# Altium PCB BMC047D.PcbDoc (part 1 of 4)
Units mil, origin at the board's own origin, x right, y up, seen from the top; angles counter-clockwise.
Board outline 4950 x 3450 mil, 6 copper layers (Top Layer, GND Layer 1, Signal Layer 1, Signal Layer 2, GND Layer 2, Bottom Layer), stack 60.7 mil thick; 323 components, 167 nets, 1114 pads, 795 vias.
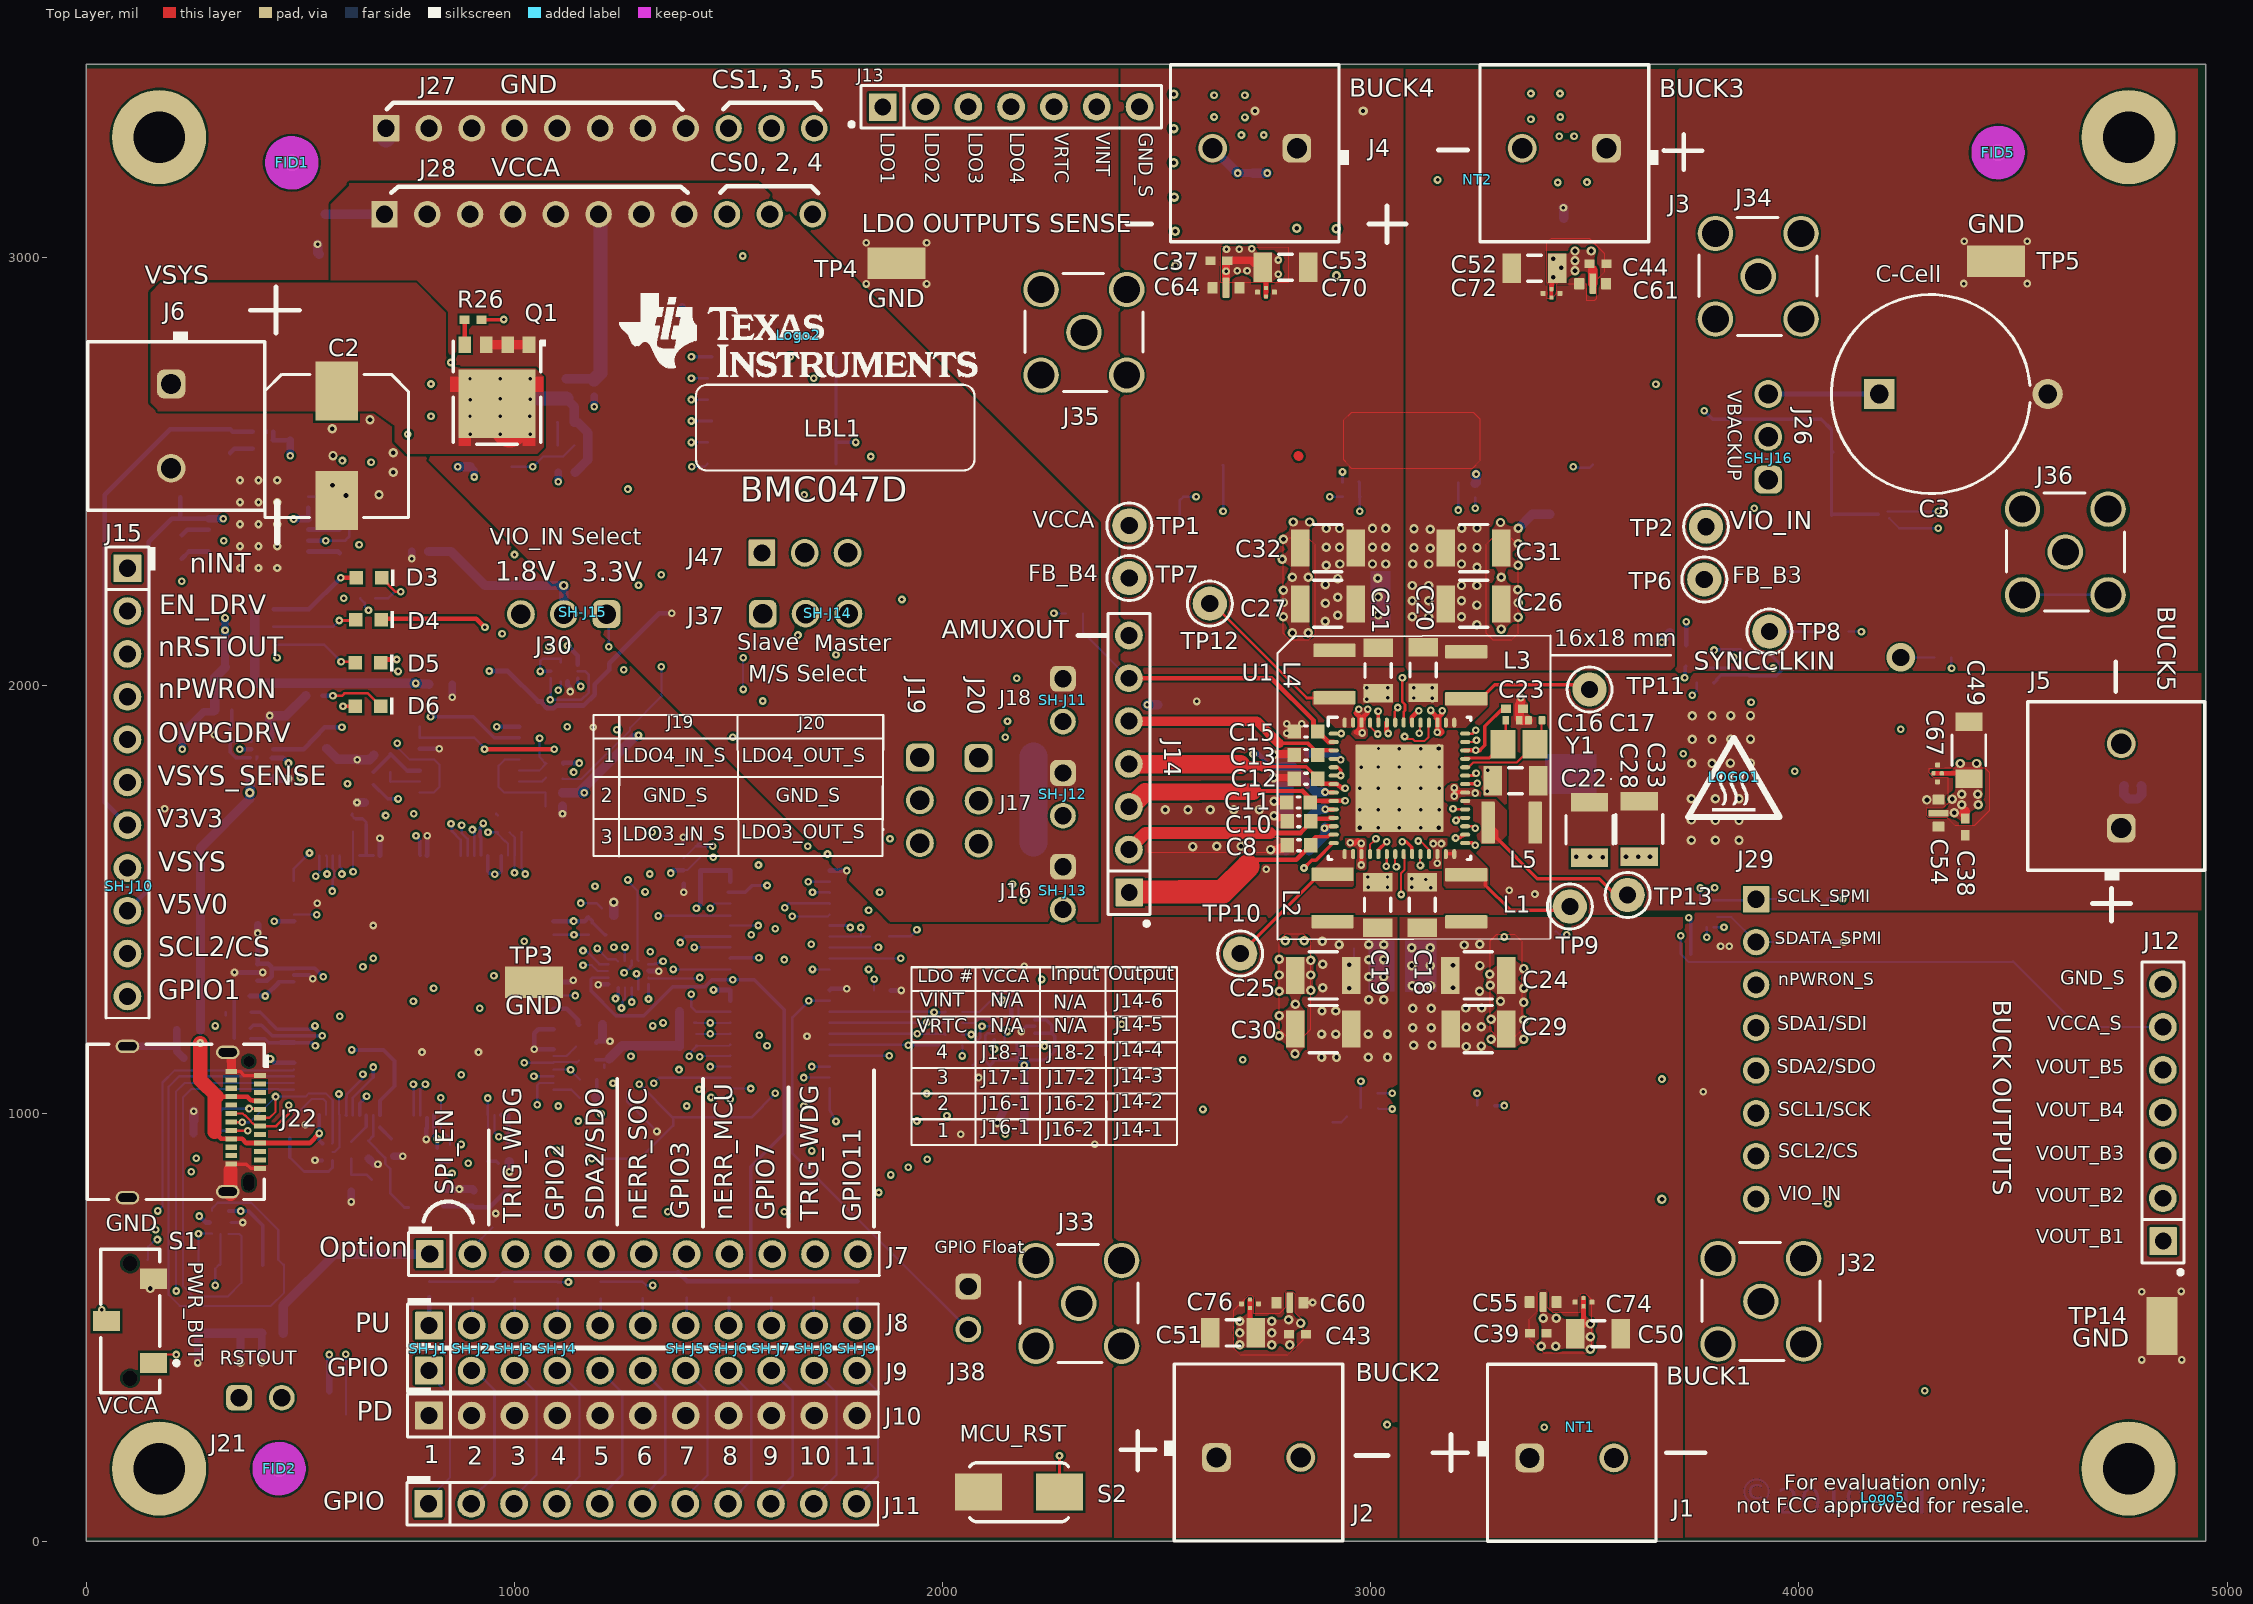
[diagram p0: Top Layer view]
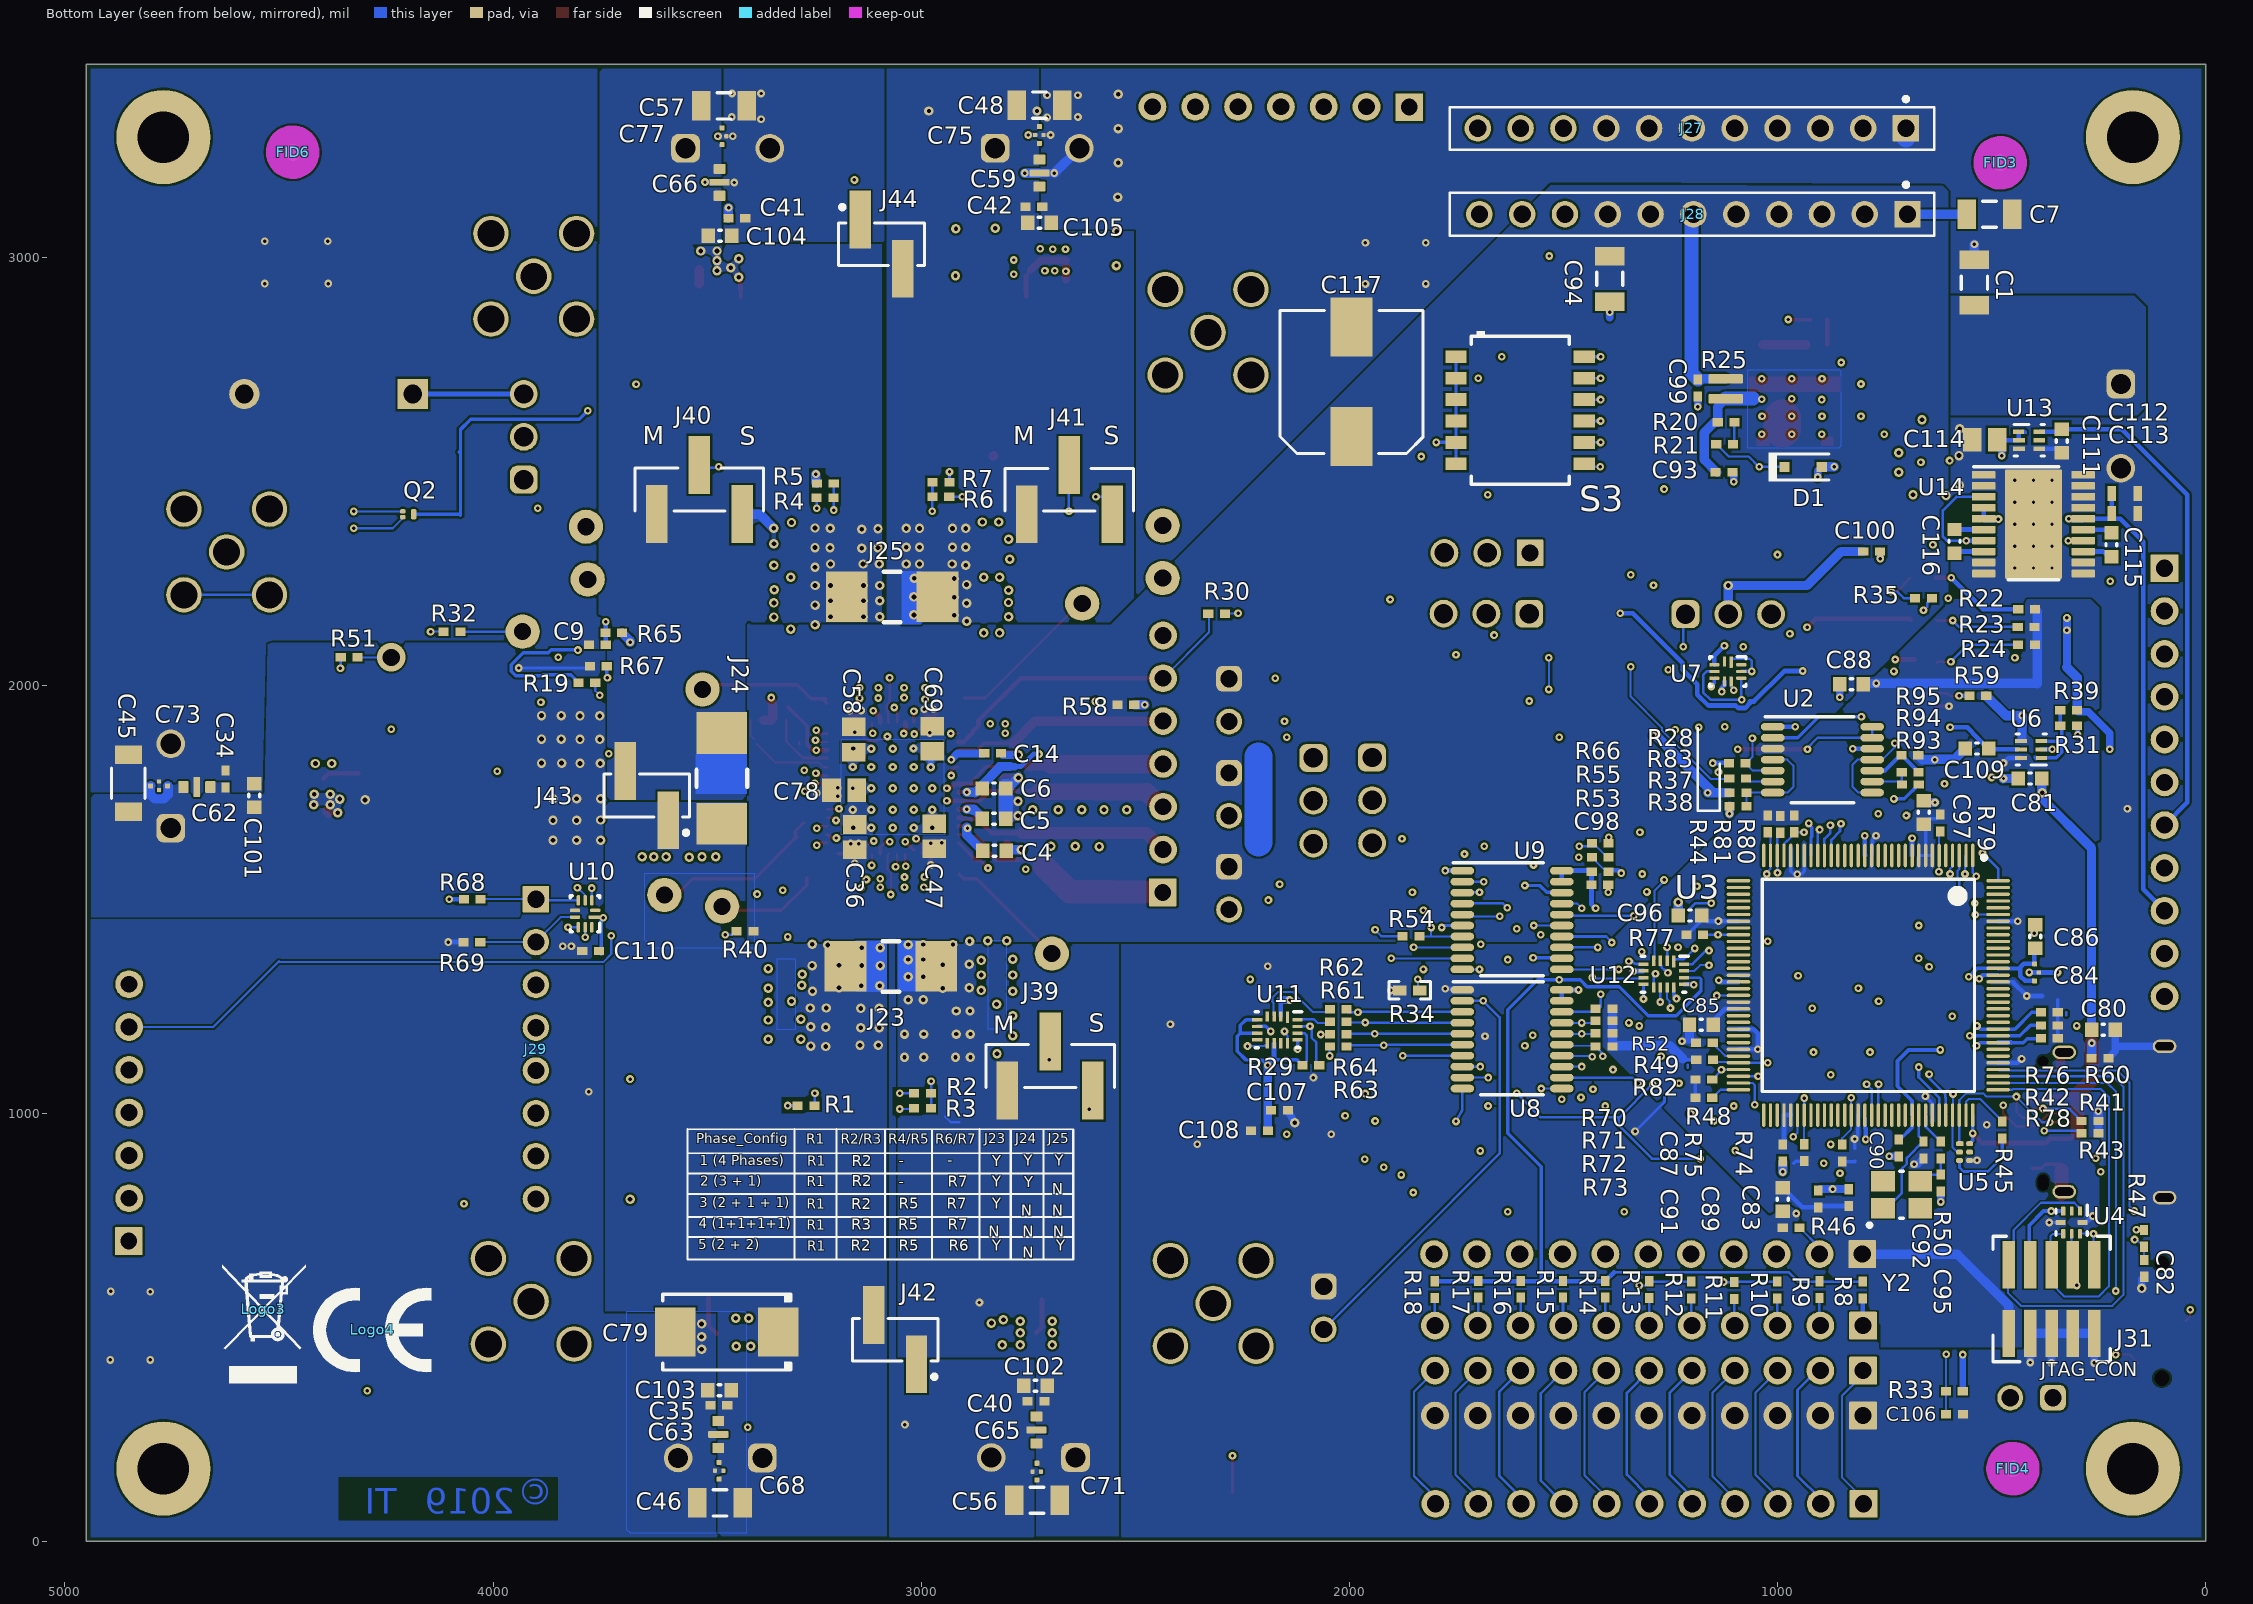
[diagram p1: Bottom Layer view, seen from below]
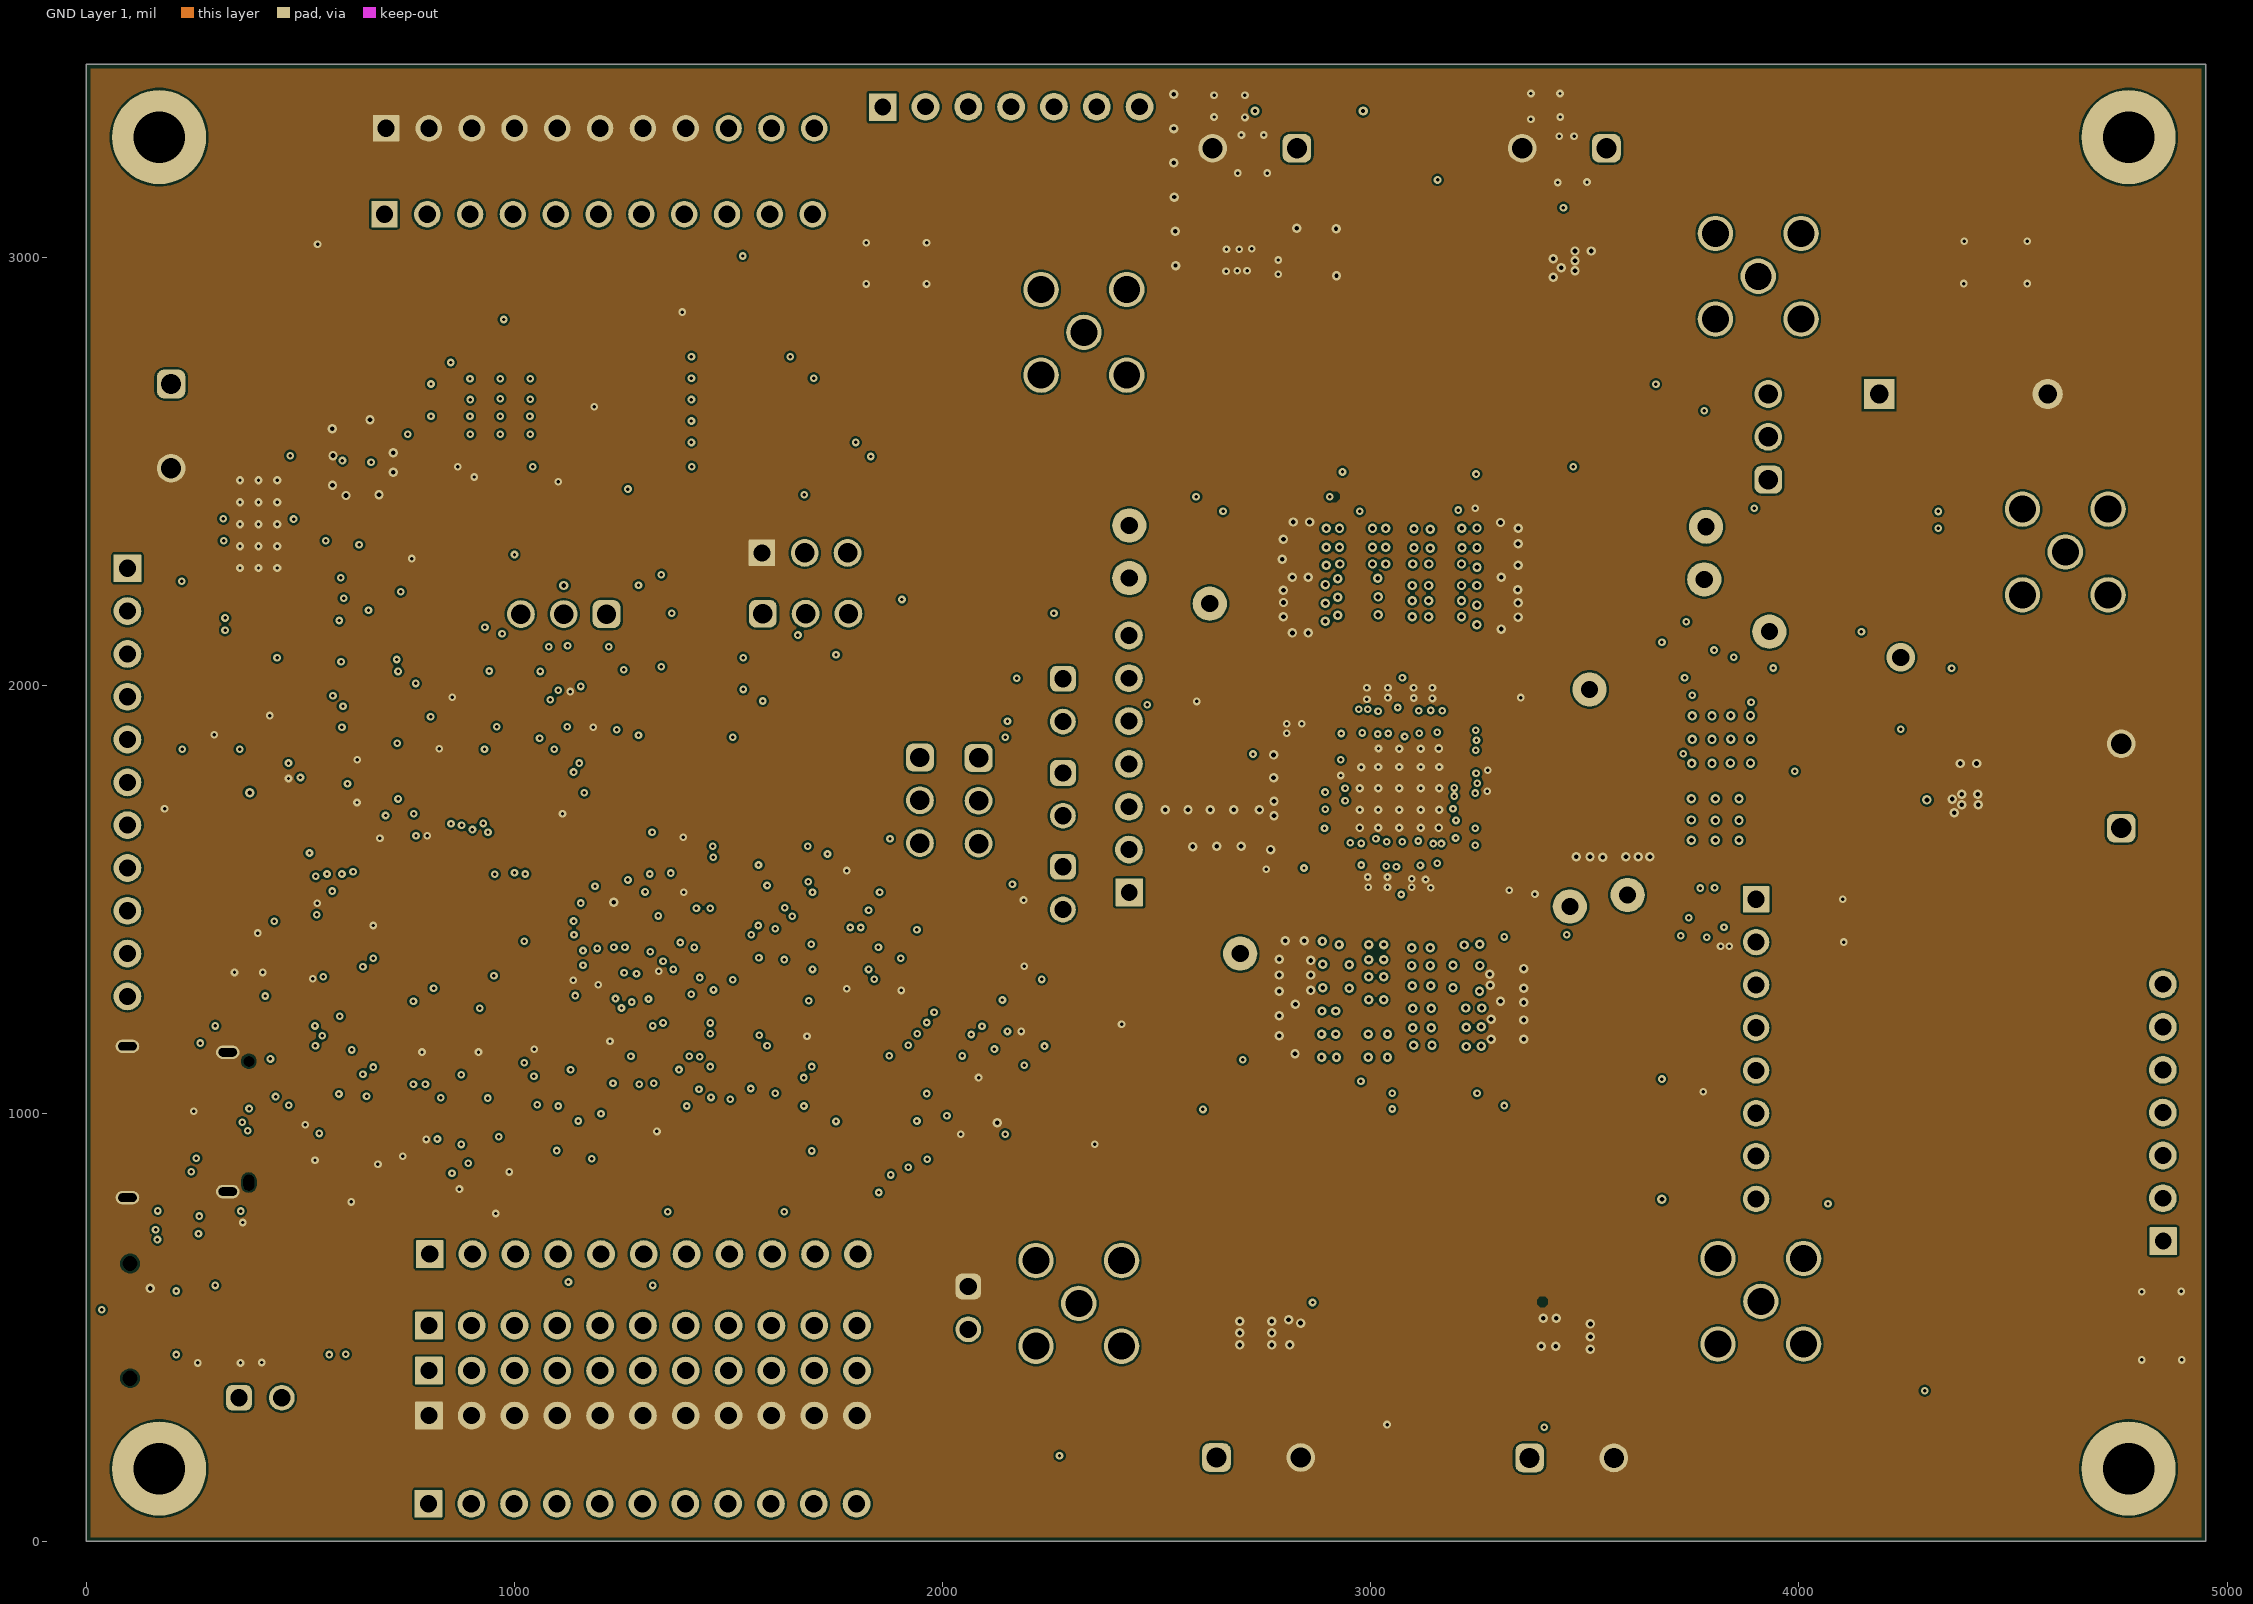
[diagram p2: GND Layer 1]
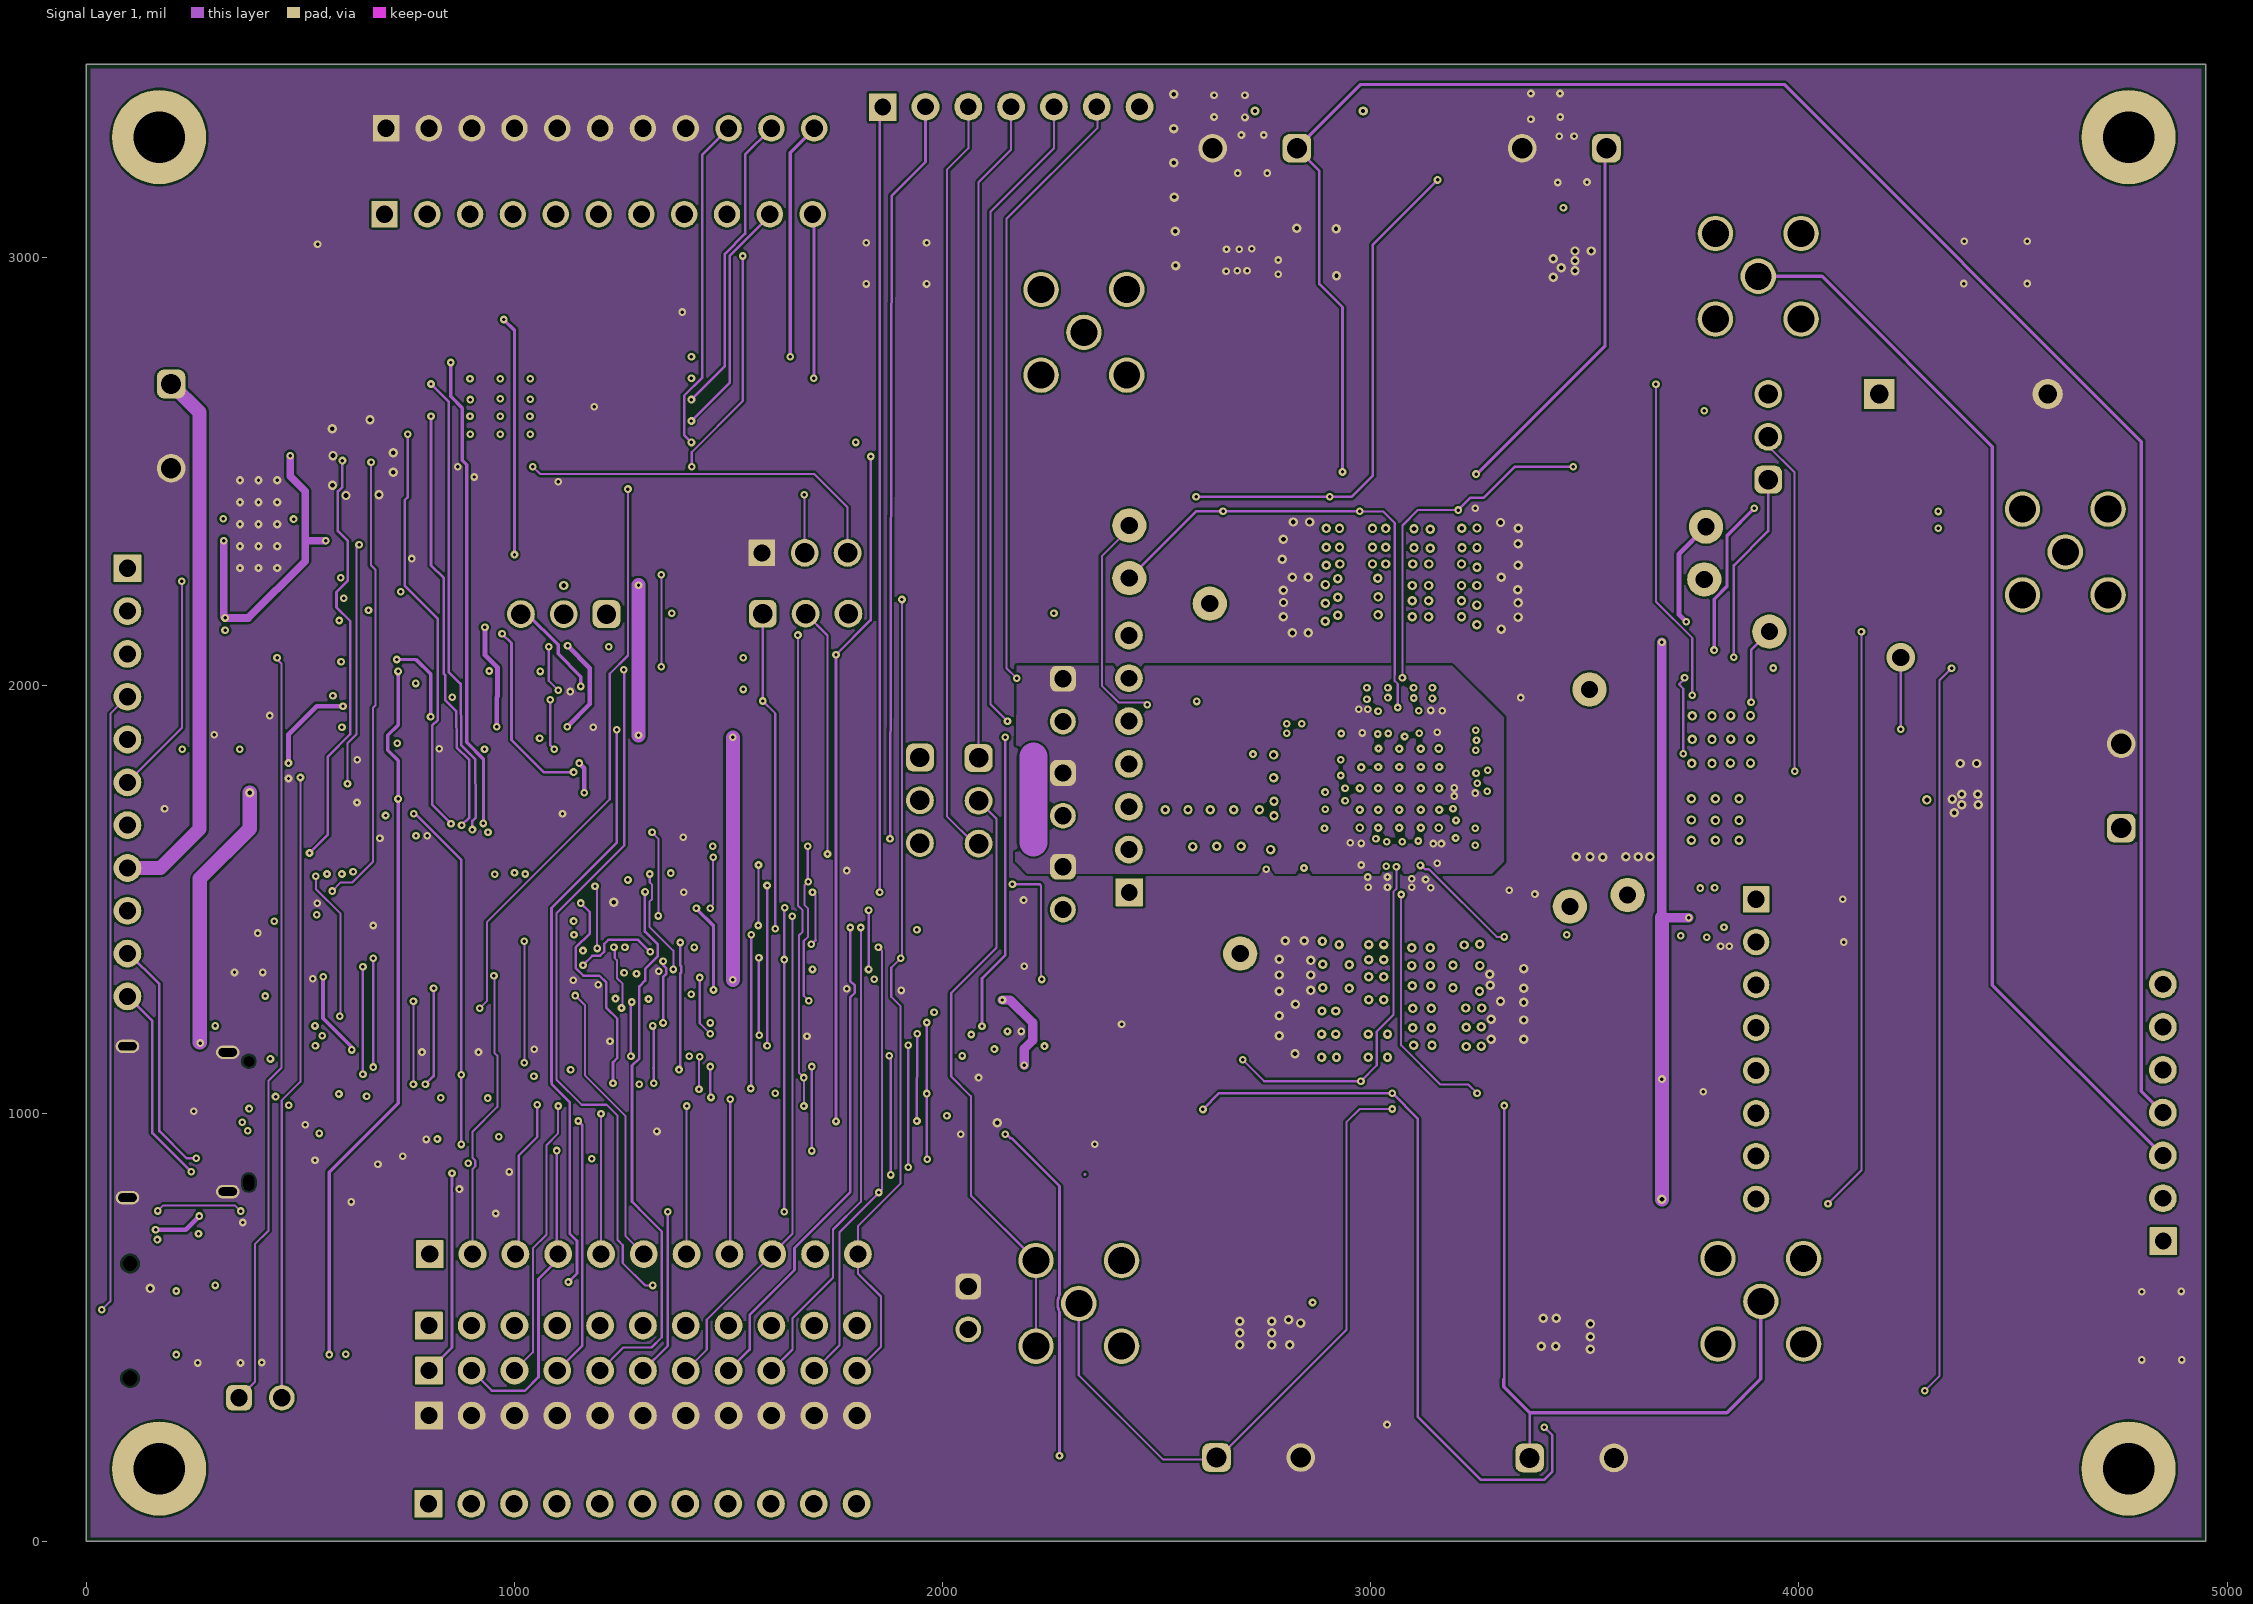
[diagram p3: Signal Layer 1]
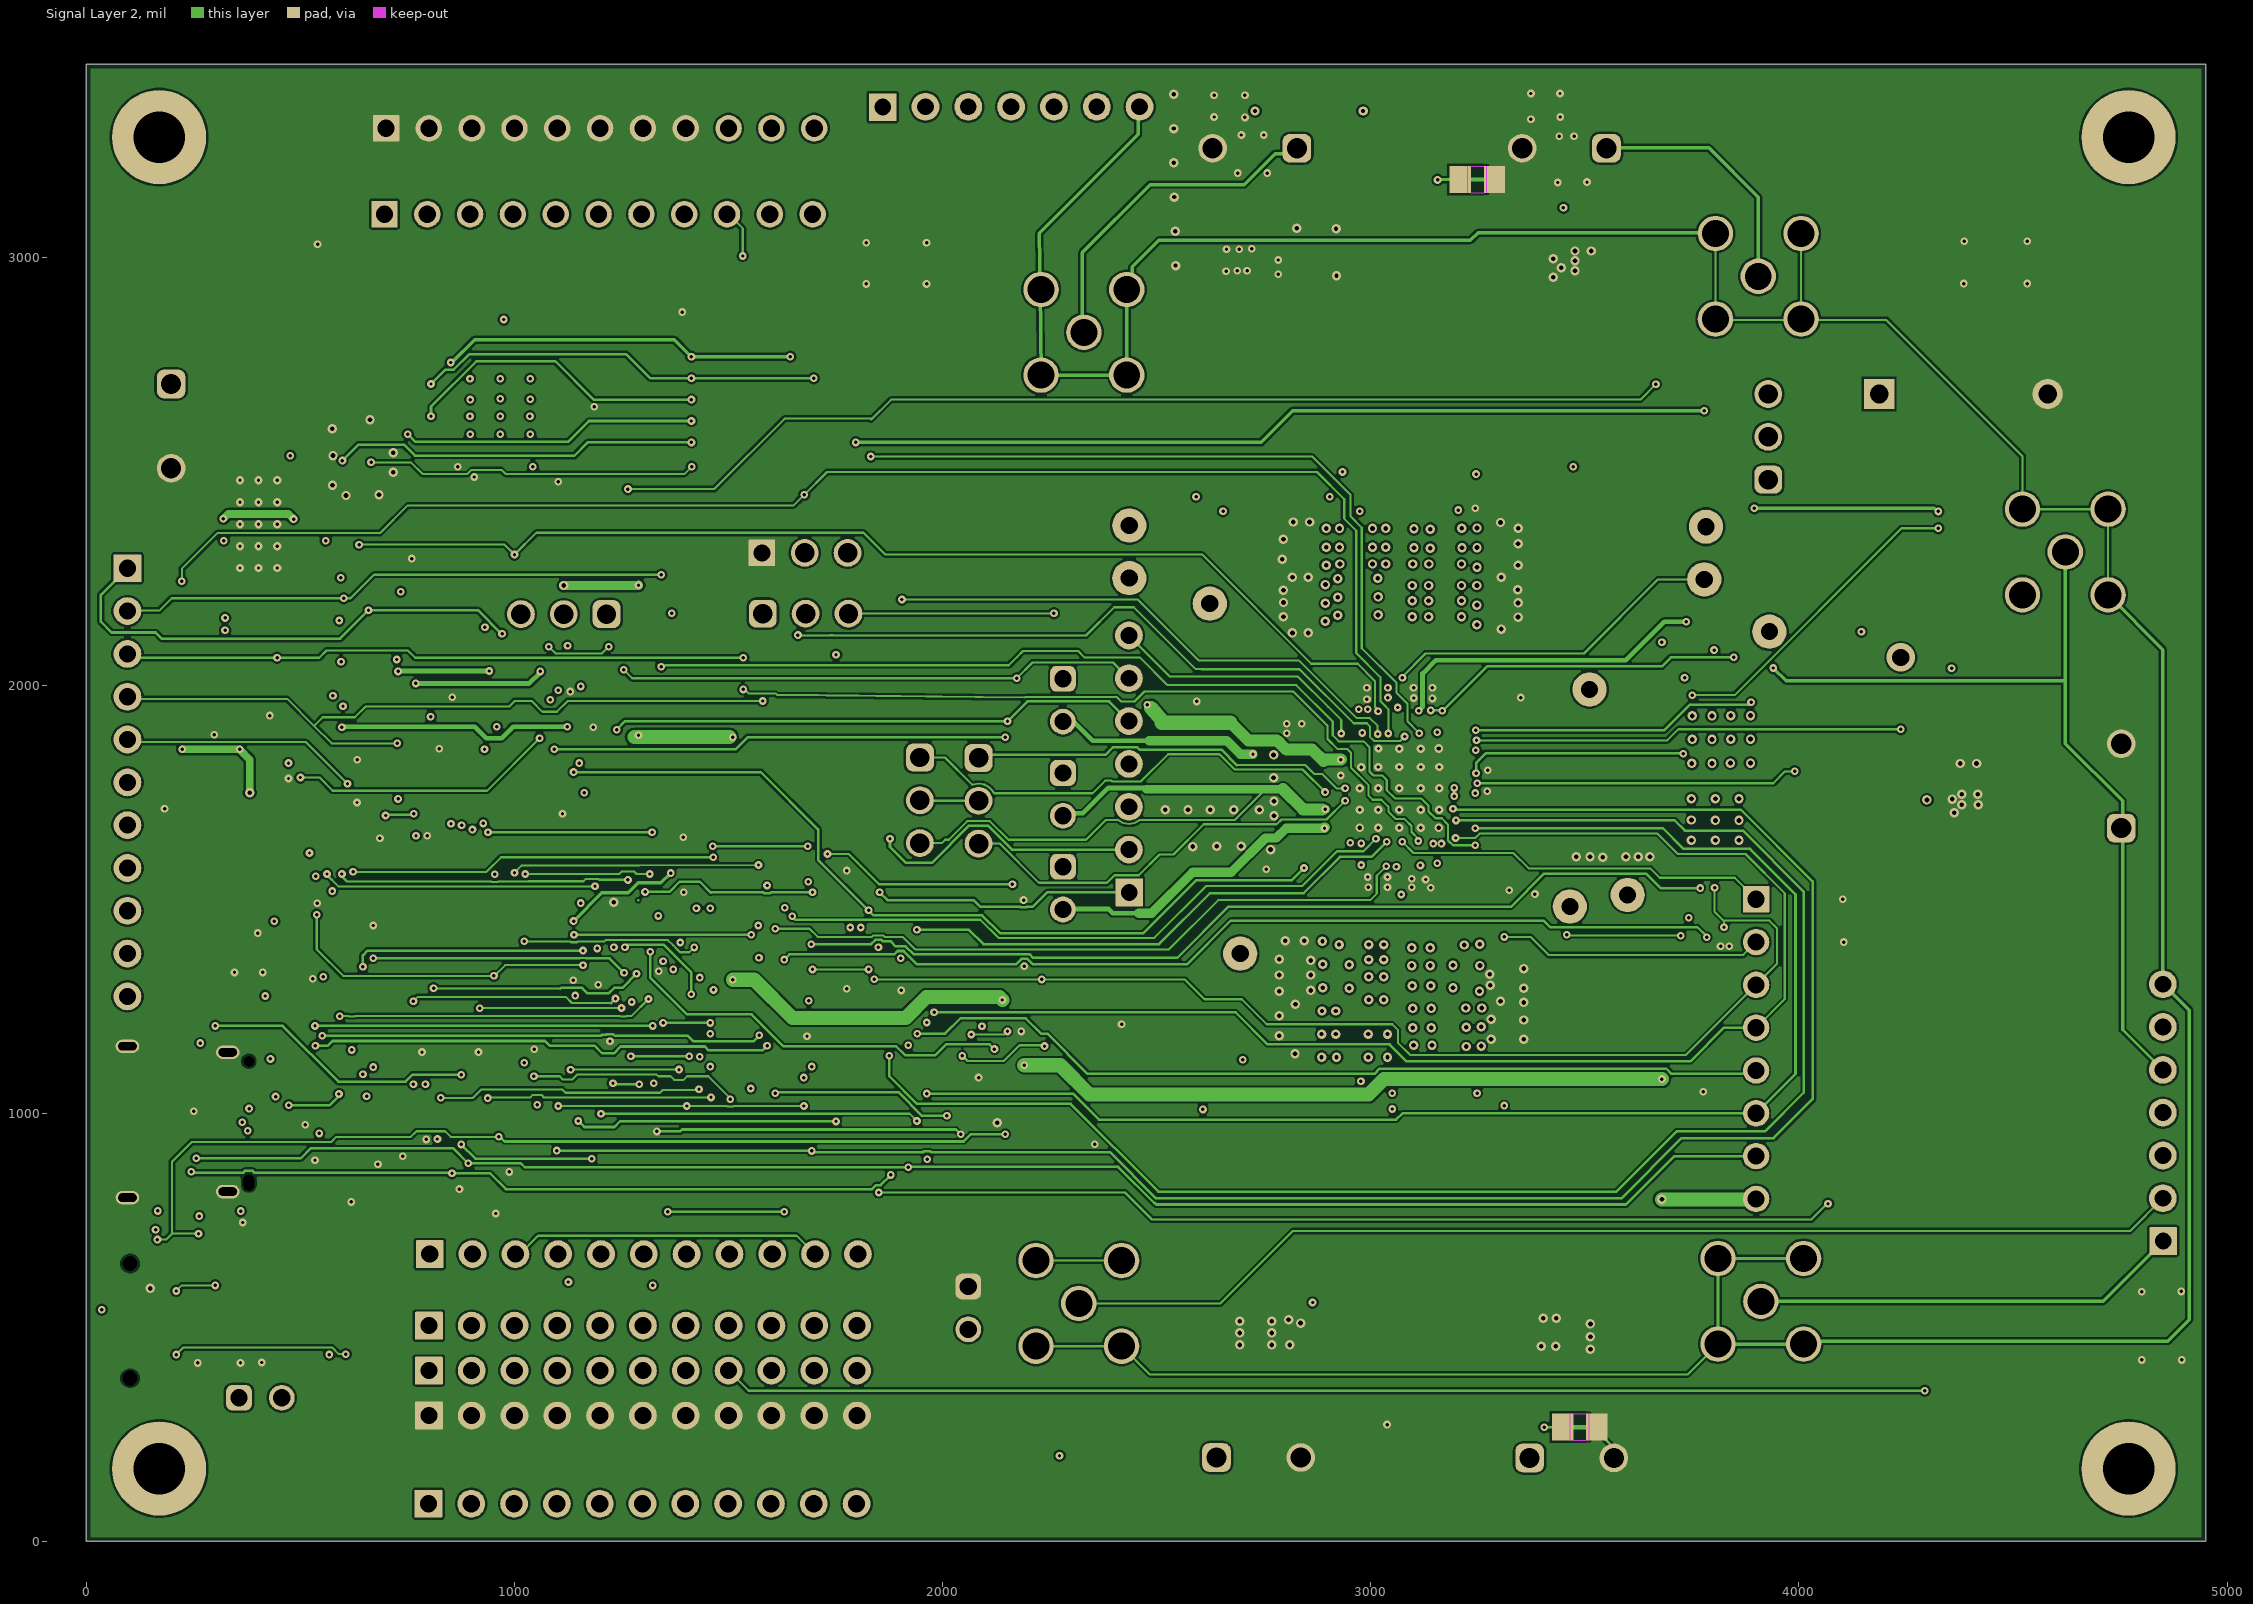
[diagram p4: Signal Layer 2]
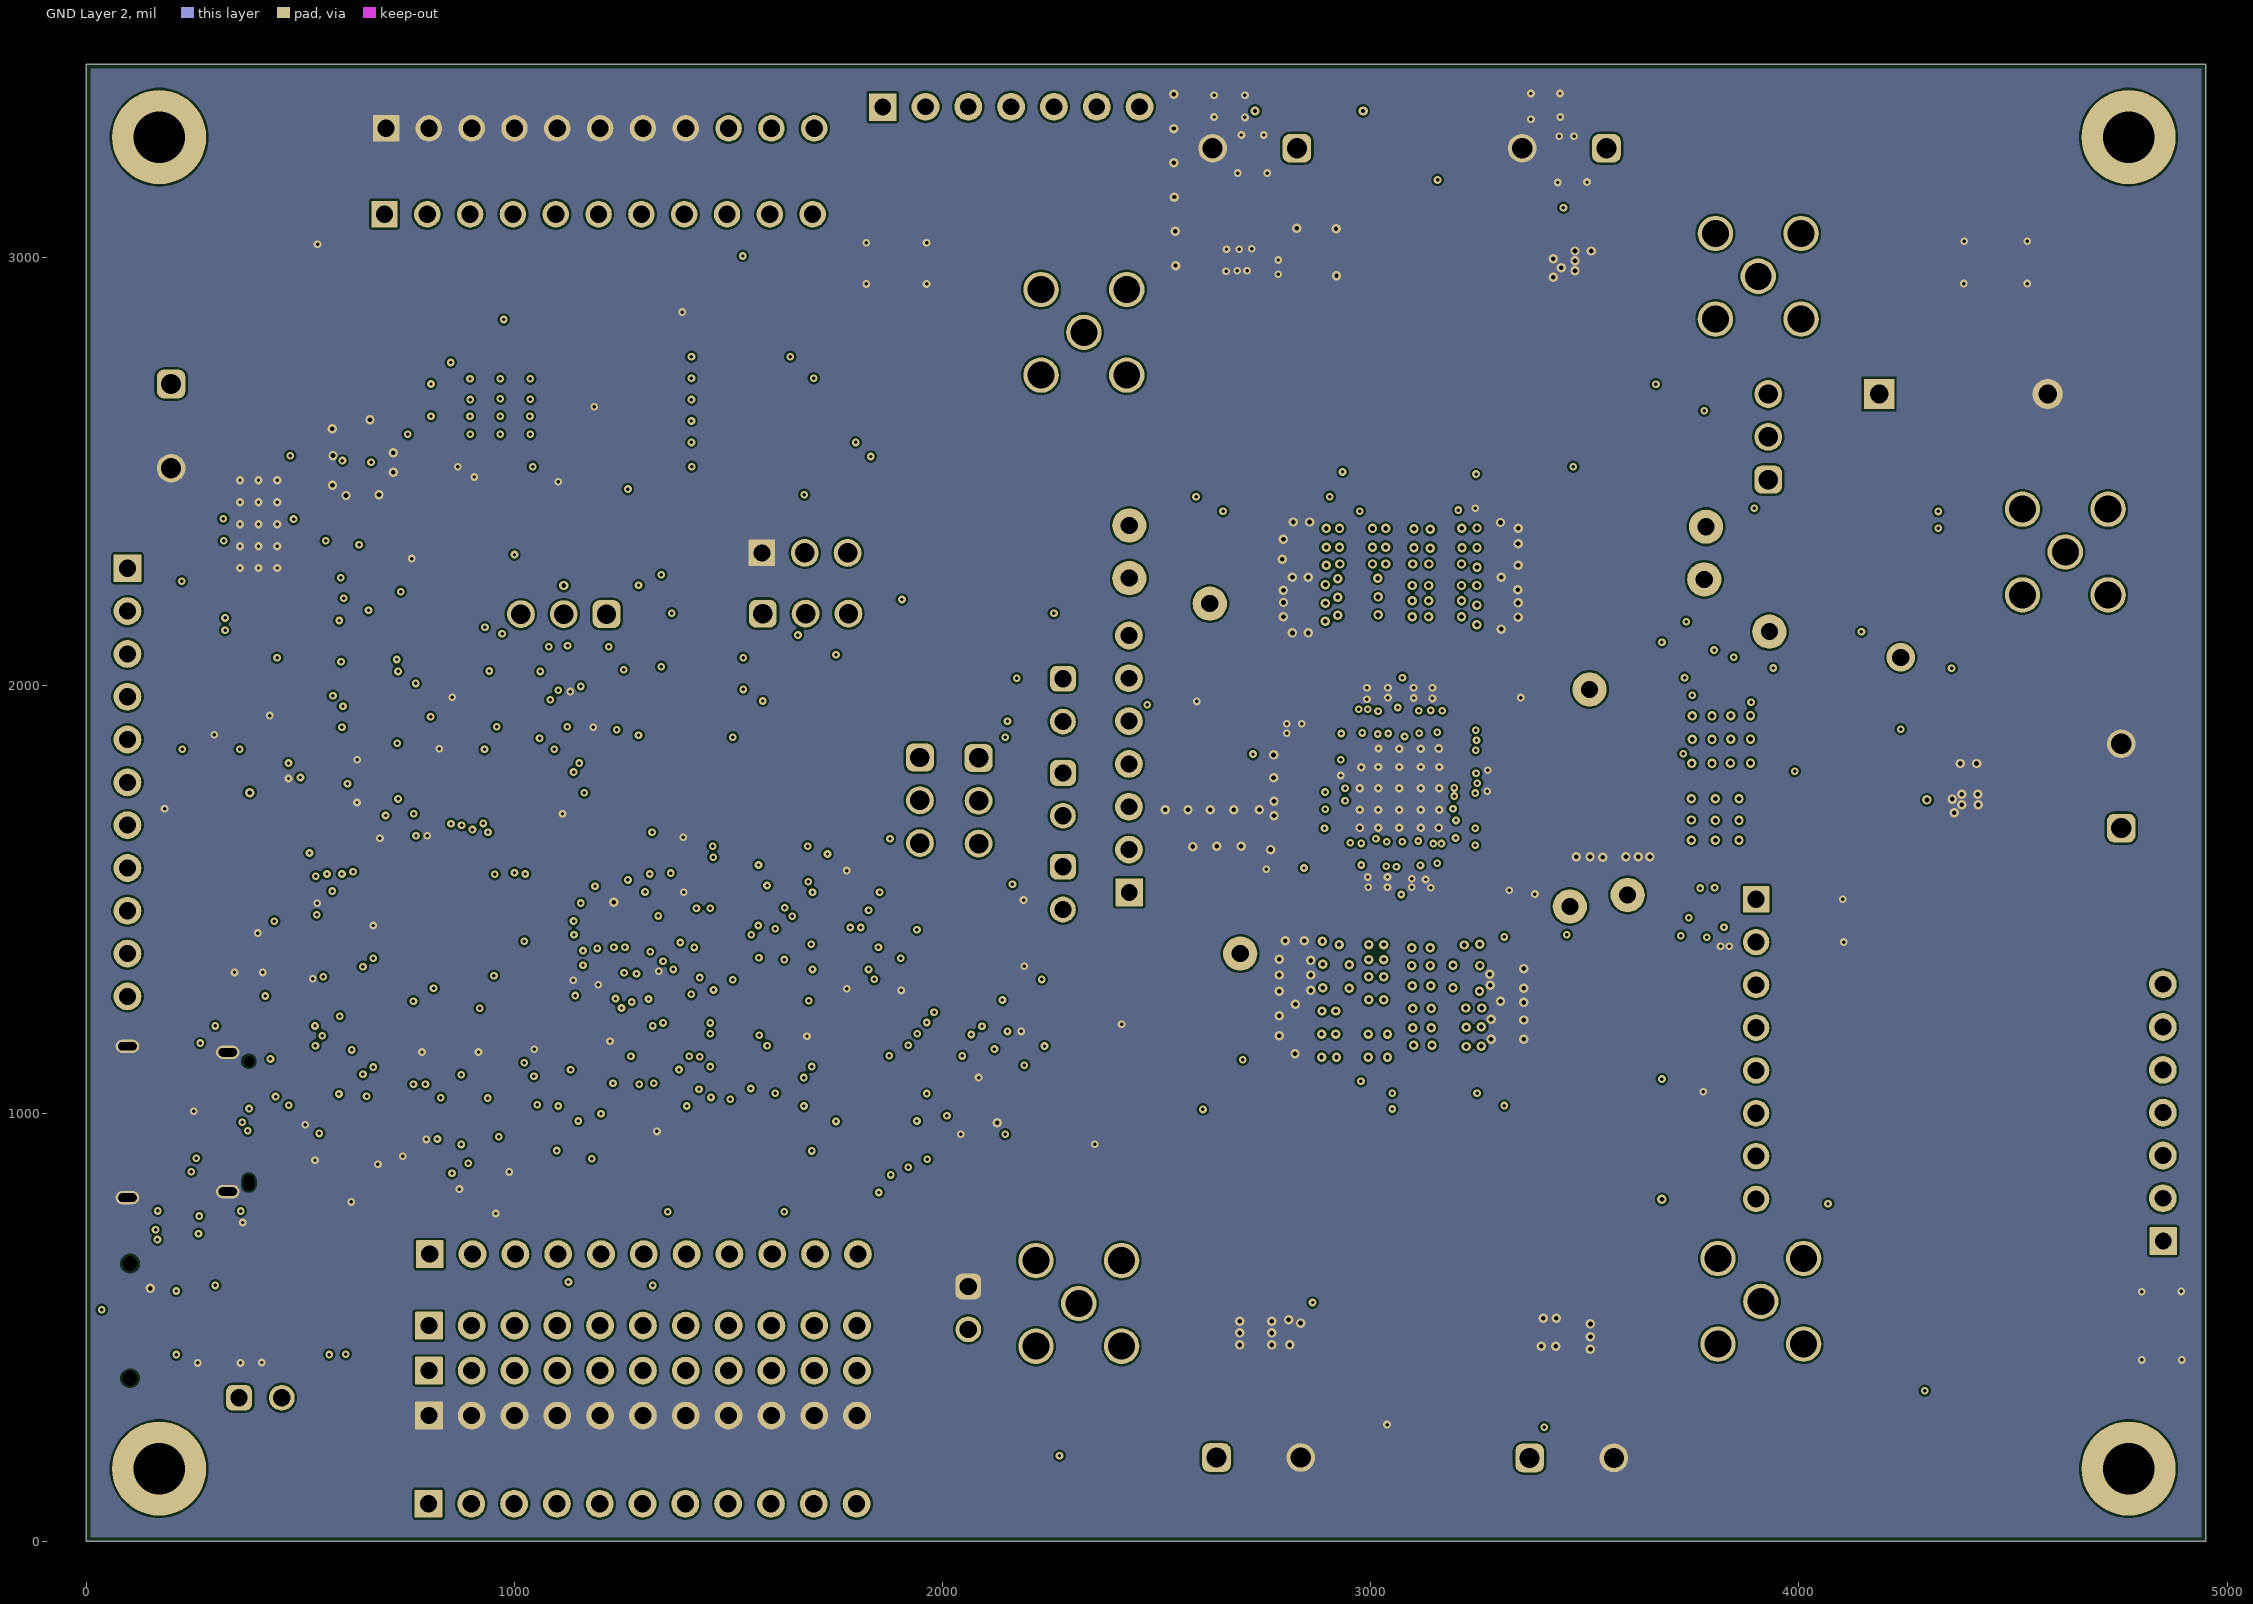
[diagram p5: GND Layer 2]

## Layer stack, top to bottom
Top Solder: solder mask 0.65, Solder Resist, Dk 3.5
Top Layer: signal copper 2.8
Dielectric1: core 5, FR-4, Dk 4.2
GND Layer 1: signal copper 1.4
Dielectric 2: prepreg 5, FR-4, Dk 4.2
Signal Layer 1: signal copper 1.4
Dielectric 3: core 29.5, FR-4, Dk 4.2
Signal Layer 2: signal copper 1.4
Dielectric 4: prepreg 5, FR-4, Dk 4.2
GND Layer 2: signal copper 1.4
Dielectric 5: core 5, FR-4, Dk 4.2
Bottom Layer: signal copper 2.8
Bottom Solder: solder mask 0.65, Solder Resist, Dk 3.5

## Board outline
0,0 4950,0 4950,3450 0,3450

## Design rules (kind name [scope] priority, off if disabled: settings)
AcuteAngle [All] p1: minimum=4.50000000000000E+0001 checktracksonly=TRUE
AssemblyTestPointUsage [All] p1: valid=2
Clearance Clearance_FID [IsKeepOut and InComponentClass('FiducialMark') vs IsPad and InComponentClass('FiducialMark')] p1: gap=5 ignorepadtopadclearanceinfootprint=TRUE
Clearance Clearance_Comp2Comp [IsPad vs IsPad] p2: gap=5 ignorepadtopadclearanceinfootprint=TRUE
Clearance Clearance_poly [InPoly] p3: gap=5 ignorepadtopadclearanceinfootprint=TRUE
Clearance Clearance_BoardEdge_MountingHoles [OnCopper and InComponentClass('Mounting Holes') vs IsKeepOut] p4: gap=40 ignorepadtopadclearanceinfootprint=TRUE except(0: Arc-Hole Track-Hole SMDPad-Hole THPad-Hole Via-Hole Fill-Hole Poly-Hole Region-Hole Text-Hole)
Clearance Clearance_BoardEdge_Poly [OnCopper and InPoly vs IsKeepOut] p5: gap=5 ignorepadtopadclearanceinfootprint=TRUE
Clearance Clearance_BoardEdge [OnCopper and Not InComponentClass('Logo') and not InComponentClass('FiducialMark') and not InRegion(1000,500,4000,800) vs IsKeepOut] p6: gap=15 ignorepadtopadclearanceinfootprint=TRUE except(0: Arc-Hole Track-Hole SMDPad-Hole THPad-Hole Via-Hole Fill-Hole Poly-Hole Region-Hole Text-Hole)
Clearance [All] p7: gap=5 ignorepadtopadclearanceinfootprint=TRUE
Clearance Clearance_Vias [IsVia vs IsVia] p8: gap=5 ignorepadtopadclearanceinfootprint=FALSE
ComponentClearance ComponentClearance_feedback [InComponent('J1*') or InComponent('J2*') or InComponent('J3*') vs HasFootprint('0402*')] p1: gap=5 collisioncheckmode=3 verticalgap=5 showdistances=FALSE
ComponentClearance ComponentClearance_Logo [InComponent('Designator1') OR InComponent('Designator2')] p2: gap=5 collisioncheckmode=3 verticalgap=5 showdistances=FALSE
ComponentClearance ComponentClearance_ScrewToNut [(HasFootprint('NY PMS 440 0025 PH')) vs (HasFootprint('Keystone_1902C'))] p3: gap=5 collisioncheckmode=3 verticalgap=10 showdistances=FALSE
ComponentClearance ComponentClearance_MountingHoles [InComponentClass('Mounting Holes') vs Not InComponent('LBL1')] p4: gap=100 collisioncheckmode=3 verticalgap=10 showdistances=FALSE
ComponentClearance ComponentClearance_SmallPassives [HasFootprint('0201*') or HasFootprint('0402*') or HasFootprint('0508') or HasFootprint('0603*') or HasFootprint('0612') or HasFootprint('0805*') or HasFootprint('0815*') or HasFootprint('0830*') or HasFootprint('1206*') or HasFootprint('1210*') or HasFootprint('1808*') or HasFootprint('1812*') or HasFootprint('1825*') or HasFootprint('2010*') or HasFootprint('2220*') or HasFootprint('2225*') or HasFootprint('2512*') or HasFootprint('2728*') or HasFootprint('3518*') or HasFootprint('IND_0805ES1') vs HasFootprint('0201*') or HasFootprint('0402*') or HasFootprint('0508') or HasFootprint('0603*') or HasFootprint('0612') or HasFootprint('0805*') or HasFootprint('0815*') or HasFootprint('0830*') or HasFootprint('1206*') or HasFootprint('1210*') or HasFootprint('1808*') or HasFootprint('1812*') or HasFootprint('1825*') or HasFootprint('2010*') or HasFootprint('2220*') or HasFootprint('2225*') or HasFootprint('2512*') or HasFootprint('2728*') or HasFootprint('3518*') or HasFootprint('IND_0805ES1')] p5: gap=2 collisioncheckmode=3 verticalgap=5 showdistances=FALSE
ComponentClearance ComponentClearance_THtoSMT [IsThruComponent vs IsSMTComponent] p6: gap=0 collisioncheckmode=3 verticalgap=0 showdistances=FALSE
ComponentClearance ComponentClearance_THtoTH [IsThruComponent vs IsThruComponent] p7: gap=0 collisioncheckmode=3 verticalgap=100000 showdistances=FALSE
ComponentClearance [All] p8: gap=0 collisioncheckmode=3 verticalgap=0 showdistances=FALSE
DiffPairsRouting [All] p1: maxlimit=100 minlimit=10 mostfreqgap=10 toplayer_minwidth=15 toplayer_maxwidth=15 toplayer_prefwidth=15 midlayer1_minwidth=15 midlayer1_maxwidth=15 midlayer1_prefwidth=15 midlayer2_minwidth=15 midlayer2_maxwidth=15 midlayer2_prefwidth=15 midlayer3_minwidth=15 midlayer3_maxwidth=15 midlayer3_prefwidth=15 midlayer4_minwidth=15 midlayer4_maxwidth=15 midlayer4_prefwidth=15 bottomlayer_minwidth=15 bottomlayer_maxwidth=15 bottomlayer_prefwidth=15 maxuncoupledlength=1000
FabricationTestPointUsage TestPointUsage [All] p1: valid=2 allowmultiple=FALSE
FabricationTestpoint Testpoint [All] p1: side=3 testpointundercomponent=TRUE minsize=40 maxsize=100 preferedsize=60 minholesize=0 maxholesize=40 preferedholesize=32 testpointgrid=1 allowsidetop=TRUE allowsidebottom=TRUE usegrid=TRUE gridtolerance=0.01
FanoutControl Fanout_LCC [IsLCC] p1: bgadir=Out bgaviamode=Centered fanoutstyle=Auto fanoutdirection=Alternating viagrid=1 // Fanout_LCC (Default Rule)
FanoutControl Fanout_BGA [IsBGA] p2: bgadir=Out bgaviamode=Centered fanoutstyle=Auto fanoutdirection=Alternating viagrid=1 // Fanout_BGA (Default Rule)
FanoutControl Fanout_Default [All] p4: bgadir=Out bgaviamode=Centered fanoutstyle=Auto fanoutdirection=Alternating viagrid=1 // Fanout_Default (Default Rule)
FanoutControl Fanout_Small [(CompPinCount < 5)] p5: bgadir=Out bgaviamode=Centered fanoutstyle=Auto fanoutdirection=OutThenIn viagrid=1 // Fanout_Small (Default Rule)
HoleSize [All] p1: absolutevalues=TRUE maxlimit=236.22 minlimit=3.94 maxpercent=80.000 minpercent=20.000
HoleToHoleClearance [All] p1: gap=7.87 allowstackedmicrovias=TRUE
MinimumAnnularRing MinimumAnnularRing_ThermalPadVias [IsVia and InAnyComponent] p1: minimumring=5
MinimumAnnularRing [All] p2: minimumring=5
MinimumSolderMaskSliver [All] p1: minsoldermaskwidth=1.97
PlaneClearance PlaneClearance_1 [OnLayer('Top Layer')] p1: clearance=7.87
PlaneClearance [All] p2: clearance=9.84
PlaneConnect PlaneConnect_via [IsVia] p1: planeconnectstyle=Relief reliefexpansion=20 reliefentries=4 reliefconductorwidth=10 reliefairgap=10
PlaneConnect [All] p2: planeconnectstyle=Direct reliefexpansion=10 reliefentries=4 reliefconductorwidth=10 reliefairgap=10
PolygonConnect PolygonConnect_tp [(InComponent('TP*') or InComponent('J4*') or InComponent('J3*') or InComponent('X7') or InComponent('X9'))] p1: connectstyle=Direct reliefconductorwidth=10 reliefentries=4 polygonreliefangle="90 Angle" airgapwidth=10
PolygonConnect PolygonConnect_logo [InComponent('Logo1')] p2: connectstyle=Direct reliefconductorwidth=10 reliefentries=4 polygonreliefangle="90 Angle" airgapwidth=10
PolygonConnect PolygonConnect_Via [IsVia] p3: connectstyle=Direct reliefconductorwidth=10 reliefentries=4 polygonreliefangle="90 Angle" airgapwidth=10
PolygonConnect [All] p4: connectstyle=Direct reliefconductorwidth=15.75 reliefentries=4 polygonreliefangle="90 Angle" airgapwidth=7.87
RoutingVias [All] p1: holewidth=7.87 width=17.72 viastyle="Through Hole" minholewidth=5 minwidth=7.87 maxholewidth=196.85 maxwidth=393.7
SilkToSilkClearance [All] p1: silktosilkclearance=0.08
SilkToSolderMaskClearance SilkscreenOverComponentPads [IsPad] p1: minsilkscreentomaskgap=0.98 clearancetoexposedcopper=TRUE
SolderMaskExpansion [All] p1: expansion=2
Width [All] p1: maxlimit=2200 minlimit=4 preferedwidth=8 minimp=50.000000 maximp=50.000000 favimp=50.000000 checkconnectedcopper=TRUE
14 further rules are at their usual default settings.

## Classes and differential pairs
component class "BMC047D USB": C80 C81 C82 C83 C84 C85 C86 C87 C88 C89 C90 C91 C92 C95 C96 C97 C98 C107 C108 C109 C110 D6 J22 J27 J28 J29 J30 J31 J38 Q2 R19 R29 R31 R34 R39 R41 R42 R43 R44 R45 R46 R47 R48 R49 R50 R52 R53 R55 R59 R60 R61 R62 R63 R64 R66 R68 R69 R70 R71 R72 R73 R74 R75 R76 R77 R78 R79 R80 R81 R82 R93 R94 R95 S2 S3 U3 U4 U5 U6 U7 U8 U9 U10 U11 U12 Y2
component class "BMC047D Main": C1 C2 C3 C4 C5 C6 C7 C8 C9 C10 C11 C12 C13 C14 C15 C16 C17 C18 C19 C20 C21 C22 C23 C24 C25 C26 C27 C28 C29 C30 C31 C32 C33 C34 C35 C36 C37 C38 C39 C40 C41 C42 C43 C44 C45 C46 C47 C48 C49 C50 C51 C52 C53 C54 C55 C56 C57 C58 C59 C60 C61 C62 C63 C64 C65 C66 C67 C68 C69 C70 C71 C72 C73 C74 C75 C76 C77 C78 C79 C93 C94 C99 C100 C101 C102 C103 C104 C105 C106 C111 C112 C113 C114 C115 C116 C117 D1 D3 D4 D5 J1 J2 J3 J4 J5 J6 J7 J8 J9 J10 J11 J12 J13 J14 J15 J16 J17 J18 J19 J20 J21 J23 J24 J25 J26 J32 J33 J34 J35 J36 J37 J39 J40 J41 J42 J43 J44 J47 J48 L1 L2 L3 L4 L5 NT1 NT2 P2 Q1 R1 R2 R3 R4 R5 R6 R7 R8 R9 R10 R11 R12 R13 R14 R15 R16 R17 R18 R20 R21 R22 R23 R24 R25 R26 R28 R30 R32 R33 R35 R37 R38 R40 R51 R54 R58 R65 R67 R83 R? S1 TP1 TP2 TP3 TP4 TP5 TP6 TP7 TP8 TP9 TP10 TP11 TP12 TP13 TP14 TP? U1 U2 U13 U14 Y1
component class AssemblyNote: ZZ1 ZZ2 ZZ3 ZZ4
component class Logo: Logo2
component class Label: LBL1
component class Header: J7 J8 J9 J10 J11 J12 J13 J14 J15 J16 J17 J18 J19 J20 J21 J26 J30 J37 J38 J39 J40 J41 J42 J43 J44 J47 J48
component class "BMC047D Hardware": FID1 FID2 FID3 FID4 FID5 FID6 H9 LBL1 LOGO1 Logo2 Logo3 Logo4 Logo5 SH-J1 SH-J2 SH-J3 SH-J4 SH-J5 SH-J6 SH-J7 SH-J8 SH-J9 SH-J10 SH-J11 SH-J12 SH-J13 SH-J14 SH-J15 SH-J16 ZZ1 ZZ2 ZZ3 ZZ4
component class FiducialMark: FID1 FID2 FID3 FID4 FID5 FID6

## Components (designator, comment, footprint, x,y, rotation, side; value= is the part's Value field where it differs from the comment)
C1 "CGA5L1X7R0J226M160AC" 1206_180L 540,2940 r90 bottom value=22uF
C2 "UUD1V151MNL1GS" SM_RADIAL_8MM 584.71,2558.68 r270 top value=150uF
C3 "DX-5R5H473U" DX-H_1150x500 4384.11,2680 r0 top value=47000uF
C4 "CGA3E1X7S1C225M080AC" 0603L 2829,1613 r180 bottom value=2.2uF
C5 "CGA3E1X7S1C225M080AC" 0603L 2830,1688 r180 bottom value=2.2uF
C6 "CGA3E1X7S1C225M080AC" 0603L 2830,1758.78 r180 bottom value=2.2uF
C7 "CGA5L1X7R0J226M160AC" 1206_180L 504.44,3100 r180 bottom value=22uF
C8 "CGA3E1X7S1C225M080AC" 0603L 2832.44,1626 r180 top value=2.2uF
C9 "GCM155C71A474KE36D" 0402L 3756.46,2094 r180 bottom value=0.47uF
C10 "CGA3E1X7S1C225M080AC" 0603L 2832,1682 r180 top value=2.2uF
C11 "CGA3E1X7S1C225M080AC" 0603L 2831.5,1726 r180 top value=2.2uF
C12 "CGA3E1X7S1C225M080AC" 0603L 2849,1781.11 r180 top value=2.2uF
C13 "CGA3E1X7S1C225M080AC" 0603L 2848.77,1837 r180 top value=2.2uF
C14 "GCM155C71A474KE36D" 0402L 2833,1840.47 r0 bottom value=0.47uF
C15 "CGA3E1X7S1C225M080AC" 0603L 2848.77,1891.69 r180 top value=2.2uF
C16 "GCM1555C1H6R0CA16" FP-GCM1555C1H6R0CA16_0402-MFG 3331,1918 r180 top
C17 "GCM1555C1H6R0CA16" FP-GCM1555C1H6R0CA16_0402-MFG 3384,1918 r0 top
C18 "CGA5L1X7R0J226M160AC" 1206_180L 3120,1487 r90 top value=22uF
C19 "CGA5L1X7R0J226M160AC" 1206_180L 3016,1487 r90 top value=22uF
C20 "CGA5L1X7R0J226M160AC" 1206_180L 3122,2035 r270 top value=22uF
C21 "CGA5L1X7R0J226M160AC" 1206_180L 3017,2034 r270 top value=22uF
C22 "CGA5L1X7R0J226M160AC" 1206_180L 3338,1777 r180 top value=22uF
C23 "GCM155R71C104KA55D" 0402L 3335.51,1944.61 r0 top value=0.1uF
C24 "47uF" 1210_280 3251,1322 r180 top
C25 "47uF" 1210_280 2889,1322 r0 top
C26 "47uF" 1210_280 3240,2190 r180 top
C27 "47uF" 1210_280 2900,2190 r0 top
C28 "47uF" 1210_280 3511,1662 r90 top
C29 "47uF" 1210_280 3251.5,1196.75 r180 top
C30 "47uF" 1210_280 2889,1196.75 r0 top
C31 "47uF" 1210_280 3240,2320 r180 top
C32 "47uF" 1210_280 2900,2320 r0 top
C33 "47uF" 1210_280 3627,1664 r90 top
C34 "GCM155R71C104KA55D" 0402L 4625,1781 r270 bottom value=0.1uF
C35 "GCM155R71C104KA55D" 0402L 3472.8,318 r180 bottom value=0.1uF
C36 "CGA4J1X7S1C106K125AC" 0805L 3155,1645 r270 bottom value=10uF
C37 "GCM155R71C104KA55D" 0402L 2645,2991.54 r180 top value=0.1uF
C38 "GCM155R71C104KA55D" 0402L 4389,1669 r90 top value=0.1uF
C39 "GCM155R71C104KA55D" 0402L 3391.15,486 r180 top value=0.1uF
C40 "GCM155R71C104KA55D" 0402L 2732,327 r180 bottom value=0.1uF
C41 "GCM155R71C104KA55D" 0402L 3430.61,3090.66 r0 bottom value=0.1uF
C42 "GCM155R71C104KA55D" 0402L 2737,3117 r0 bottom value=0.1uF
C43 "GCM155R71C104KA55D" 0402L 2829.08,483.6 r180 top value=0.1uF
C44 "GCM155R71C104KA55D" 0402L 3530.69,2984.58 r180 top value=0.1uF
C45 "GCM31CD70G476ME" 1206_190 4852,1771 r90 bottom
C46 "GCM31CD70G476ME" 1206_190L 3470,90 r0 bottom
C47 "CGA4J1X7S1C106K125AC" 0805L 2970,1647 r90 bottom value=10uF
C48 "GCM31CD70G476ME" 1206_190L 2724,3355 r180 bottom
C49 "GCM31CD70G476ME" 1206_190 4397,1848.04 r270 top
C50 "GCM31CD70G476ME" 1206_190L 3531.15,485 r180 top
C51 "GCM31CD70G476ME" 1206_190L 2678,487 r0 top
C52 "GCM31CD70G476ME" 1206_190L 3382,2974 r0 top
C53 "GCM31CD70G476ME" 1206_190L 2800.85,2976 r180 top
C54 "10uF" NFM18HC 4326,1701 r270 top
C55 "10uF" NFM18HC 3402.5,559 r0 top
C56 "GCM31CD70G476ME" 1206_190L 2730,96 r0 bottom
C57 "GCM31CD70G476ME" 1206_190L 3461,3353 r180 bottom
C58 "CGA4J1X7S1C106K125AC" 0805L 3158,1873 r270 bottom value=10uF
C59 "10uF" NFM18HC 2724,3196 r270 bottom
C60 "10uF" NFM18HC 2811,557.63 r0 top
C61 "10uF" NFM18HC 3518.35,2937.65 r0 top
C62 "10uF" NFM18HC 4692,1762.22 r180 bottom
C63 "10uF" NFM18HC 3474,250 r90 bottom
C64 "10uF" NFM18HC 2662,2928 r180 top
C65 "10uF" NFM18HC 2731,260.5 r270 bottom
C66 "10uF" NFM18HC 3471,3174.5 r270 bottom
C67 "NFM15HC105D0G3" FP-NFM15HC105D0G3_0402-MFG 4324,1794 r270 top
C68 "NFM15HC105D0G3" FP-NFM15HC105D0G3_0402-MFG 3471.92,165.14 r270 bottom
C69 "CGA4J1X7S1C106K125AC" 0805L 2974,1875 r270 bottom value=10uF
C70 "NFM15HC105D0G3" FP-NFM15HC105D0G3_0402-MFG 2755,2917.84 r0 top
C71 "NFM15HC105D0G3" FP-NFM15HC105D0G3_0402-MFG 2730,163 r270 bottom
C72 "NFM15HC105D0G3" FP-NFM15HC105D0G3_0402-MFG 3422,2915 r0 top
C73 "NFM15HC105D0G3" FP-NFM15HC105D0G3_0402-MFG 4780,1764.84 r180 bottom
C74 "NFM15HC105D0G3" FP-NFM15HC105D0G3_0402-MFG 3497,559 r180 top
C75 "NFM15HC105D0G3" FP-NFM15HC105D0G3_0402-MFG 2724,3285 r270 bottom
C76 "NFM15HC105D0G3" FP-NFM15HC105D0G3_0402-MFG 2718,555 r0 top
C77 "NFM15HC105D0G3" FP-NFM15HC105D0G3_0402-MFG 3465,3282 r90 bottom
C78 "CGA4J1X7S1C106K125AC" 0805L 3180,1755 r180 bottom value=10uF
C79 "T510X687K006AGA023" 7343-40 3454.08,489 r0 bottom value=680uF
C80 "C0603C332K5RACTU" 0603L 239,1195 r180 bottom value=3300pF
C81 "CGA3E1X7S1C225M080AC" 0603L 410,1782 r0 bottom value=2.2uF
C82 "GCM155R71C104KA55D" 0402L 143,638 r270 bottom value=0.1uF
C83 "GCM155R71C104KA55D" 0402L 834,803 r90 bottom value=0.1uF
C84 "NFM15HC105D0G3" FP-NFM15HC105D0G3_0402-MFG 399.5,1329 r270 bottom
C85 "CGA3E1X7S1C225M080AC" 0603L 1178,1207 r0 bottom value=2.2uF
C86 "CGA3E1X7S1C225M080AC" 0603L 398,1413 r90 bottom value=2.2uF
C87 "GCM155R71C104KA55D" 0402L 988,907 r90 bottom value=0.1uF
C88 "CGA3E1X7S1C225M080AC" 0603L 827.37,2002 r0 bottom value=2.2uF
C89 "GCM155R71C104KA55D" 0402L 905,800 r90 bottom value=0.1uF
C90 "GCM155R71C104KA55D" 0402L 717,919 r270 bottom value=0.1uF
C91 "CGA3E1X7S1C225M080AC" 0603L 988,799 r270 bottom value=2.2uF
C92 "GCM1555C1H120JA16J" 0402L 659,914 r270 bottom value=12pF
C93 "GCM155R71C104KA55D" 0402L 1124.87,2497.15 r180 bottom value=0.1uF
C94 "CGA5L1X7R0J226M160AC" 1206_180L 1392,2949.15 r270 bottom value=22uF
C95 "GCM1555C1H120JA16J" 0402L 619,837 r270 bottom value=12pF
C96 "CGA3E1X7S1C225M080AC" 0603L 1204.56,1462 r180 bottom value=2.2uF
C97 "CGA3E1X7S1C225M080AC" 0603L 658.5,1703 r270 bottom value=2.2uF
C98 "GCM155R71C104KA55D" 0402L 1415,1534 r180 bottom value=0.1uF
C99 "GCM155R71C104KA55D" 0402L 1186,2694 r270 bottom value=0.1uF
C100 "GCM155R71C104KA55D" 0402L 780,2312.2 r180 bottom value=0.1uF
C101 "C0603C332K5RACTU" 0603L 4558,1742.02 r90 bottom value=3300pF
C102 "C0603C332K5RACTU" 0603L 2733,364 r0 bottom value=3300pF
C103 "C0603C332K5RACTU" 0603L 3471,353 r0 bottom value=3300pF
C104 "C0603C332K5RACTU" 0603L 3470,3050 r180 bottom value=3300pF
C105 "C0603C332K5RACTU" 0603L 2724,3080 r180 bottom value=3300pF
C106 "GCM155R71C104KA55D" 0402L 586.56,297 r0 bottom value=0.1uF
C107 "GCM155R71C104KA55D" 0402L 2163,1006.86 r0 bottom value=0.1uF
C108 "GCM155R71C104KA55D" 0402L 2210.17,959.24 r180 bottom value=0.1uF
C109 "CGA3E1X7S1C225M080AC" 0603L 534,1852 r0 bottom value=2.2uF
C110 "GCM155R71C104KA55D" 0402L 3772,1379 r180 bottom value=0.1uF
C111 "CGA3E1X7S1C225M080AC" 0603L 336,2570 r90 bottom value=2.2uF
C112 "GRM188R60J226MEA0D" 0603S 189,2448 r180 bottom value=22uF
C113 "GRM188R60J226MEA0D" 0603S 189,2401 r180 bottom value=22uF
C114 "CGA4J1X7S1C106K125AC" 0805L 516,2573 r0 bottom value=10uF
C115 "CGA3E1X7S1C225M080AC" 0603L 220,2328 r90 bottom value=2.2uF
C116 "CGA3E1X7S1C225M080AC" 0603L 586.56,2336 r90 bottom value=2.2uF
C117 "UUD1C471MNL1GS" SM_RADIAL_8MM 1994.93,2708.22 r90 bottom value=470uF
D1 "MM3Z10VST1G" SOD-323 940,2509.69 r180 bottom value=10V
D3 "LB Q39G-L2N2-35-1" "LB Q39G_BLUE" 660,2251 r0 top value=Blue
D4 "LB Q39G-L2N2-35-1" "LB Q39G_BLUE" 659,2153 r0 top value=Blue
D5 "LB Q39G-L2N2-35-1" "LB Q39G_BLUE" 658,2052 r0 top value=Blue
D6 "LB Q39G-L2N2-35-1" "LB Q39G_BLUE" 658,1951 r0 top value=Blue
FID1 "Fiducial" Fiducial10-30 480,3220 r0 top
FID2 "Fiducial" Fiducial10-30 450,170 r0 top
FID3 "Fiducial" Fiducial10-30 480,3220 r180 bottom
FID4 "Fiducial" Fiducial10-30 450,170 r180 bottom
FID5 "Fiducial" Fiducial10-30 4465,3244 r0 top
FID6 "Fiducial" Fiducial10-30 4468,3245 r180 bottom
J1 "1792863" Phoenix_1792863 3469.43,195 r0 top
J2 "1792863" Phoenix_1792863 2738,196 r0 top
J3 "1792863" Phoenix_1792863 3452,3254 r180 top
J4 "1792863" Phoenix_1792863 2729,3254 r180 top
J5 "1792863" Phoenix_1792863 4753,1764.57 r90 top
J6 "1792863" Phoenix_1792863 198,2605 r270 top
J7 "TSW-111-07-G-S" TSW-111-07-G-S 1302,671 r0 top
J8 "TSW-111-07-G-S" TSW-111-07-G-S 1300,504 r0 top
J9 "TSW-111-07-G-S" TSW-111-07-G-S 1300,399 r0 top
J10 "TSW-111-07-G-S" TSW-111-07-G-S 1300,294 r0 top
J11 "TSW-111-07-G-S" TSW-111-07-G-S 1299,88 r0 top
J12 "TSW-107-07-G-S" TSW-107-XX-XXX-S 4850,1001.5 r90 top
J13 "TSW-107-07-G-S" TSW-107-XX-XXX-S 2160,3351 r0 top
J14 "TSW-107-07-G-S" TSW-107-XX-XXX-S 2435,1816 r90 top
J15 "TSW-111-07-G-S" TSW-111-07-G-S 96,1773 r270 top
J16 "TSW-102-23-T-S" Samtec_TSW-102-23-X-S 2281,1526 r270 top
J17 "TSW-102-23-T-S" Samtec_TSW-102-23-X-S 2281,1745 r270 top
J18 "TSW-102-23-T-S" Samtec_TSW-102-23-X-S 2281,1965 r270 top
J19 "61300311121" WURTH_61300311121#1 1947,1731 r270 top
J20 "61300311121" WURTH_61300311121#1 2084,1730 r270 top
J21 "TSW-102-23-T-S" Samtec_TSW-102-23-X-S 406.5,335.56 r0 top
J22 "12401610E4#2A" Amphenol_12401610E4_2A 379.46,979.77 r270 top
J23 "S1911-46R" HARWIN_S1911-46R 3071,1343 r180 bottom
J24 "S1911-46R" HARWIN_S1911-46R 3465.61,1782.42 r270 bottom
J25 "S1911-46R" HARWIN_S1911-46R 3068,2206 r0 bottom
J26 "61300311121" WURTH_61300311121#1 3928.37,2580 r90 top
J27 "ESQ-111-14-T-S" FP-ESQ-111-14-T-S_HDR11-MFG#1 1200,3300 r0 bottom
J28 "ESQ-111-14-T-S" FP-ESQ-111-14-T-S_HDR11-MFG#2 1200,3100 r0 bottom
J29 "ESQ-108-14-T-S" FP-ESQ-108-14-T-S_HDR8-MFG 3900,1150 r270 bottom
J30 "61300311121" WURTH_61300311121#1 1115,2166 r180 top
J31 "SH-105-01-F-DV-K" Samtec_FTSH-105-01-x-DV-K 360,566.12 r90 bottom
J32 "SMA-J-P-H-ST-TH1" SAMTEC_SMA-J-P-H-ST-TH1 3911,560.88 r0 top
J33 "SMA-J-P-H-ST-TH1" SAMTEC_SMA-J-P-H-ST-TH1 2318,556 r0 top
J34 "SMA-J-P-H-ST-TH1" SAMTEC_SMA-J-P-H-ST-TH1 3905,2955 r0 top
J35 "SMA-J-P-H-ST-TH1" SAMTEC_SMA-J-P-H-ST-TH1 2330.01,2824.07 r0 top
J36 "SMA-J-P-H-ST-TH1" SAMTEC_SMA-J-P-H-ST-TH1 4622.18,2311 r0 top
J37 "61300311121" WURTH_61300311121#1 1680,2167 r0 top
J38 "TSW-102-23-T-S" Samtec_TSW-102-23-X-S 2059.94,545.37 r270 top
J39 "TSM-103-01-L-SV" Samtec_TSM-103-01-X-SV 2699,1110.5 r0 bottom
J40 "TSM-103-01-L-SV" Samtec_TSM-103-01-X-SV 3518,2457 r0 bottom
J41 "TSM-103-01-L-SV" Samtec_TSM-103-01-X-SV 2654,2456.5 r0 bottom
J42 "TSM-102-01-T-SV-P-TR" Samtec_TSM-102-01-T-SV-P-TR 3061,471.27 r0 bottom
J43 "TSM-102-01-T-SV-P-TR" Samtec_TSM-102-01-T-SV-P-TR 3641,1741.96 r0 bottom
J44 "TSM-102-01-T-SV-P-TR" Samtec_TSM-102-01-T-SV-P-TR 3092.77,3030 r180 bottom
J47 "61300311121" WURTH_61300311121#2 1678,2309 r0 top
L1 "470nH" TFM322512 3223,1502 r270 top
L2 "470nH" TFM322512 2911,1503 r270 top
L3 "470nH" TFM322512 3223,2023 r90 top
L4 "470nH" TFM322512 2915,2026 r90 top
L5 "470nH" TFM322512 3329,1679 r0 top
LBL1 "THT-14-423-10" Label_650x200 1749.07,2601.54 r0 top
LOGO1 "CAUTION HOT SURFACE" IEC_HotSurface_Small 3848,1784.58 r0 top
Logo2 "Texas Instruments" TI_Stacked_Overlay_Small 1662.92,2817.46 r0 top
Logo3 "WEEE logo" WEEE_Minimum 4536.92,542 r180 bottom
Logo4 "CE Mark" CE_Mark_5mm 4282,494 r180 bottom
Logo5 "FCC disclaimer" FCC_disclaimer_stacked 4196,102 r0 top
NT1 "Net-Tie" Net-Tie_0805_HV_NoOverlay 3488,267 r0 top net-tie
NT2 "Net-Tie" Net-Tie_0805_HV_NoOverlay 3249,3181 r0 top net-tie
Q1 "NVMFS4C05NT1G" SO-8FL 959,2684.91 r270 top value=30V
Q2 "CSD13381F4" YJC0003A 4198.16,2399.2 r180 bottom value=12V
R1 "RK73Z1ETTP" 0402L 3269.31,1018 r0 bottom value=0
R2 "RK73Z1ETTP" 0402L 2997.12,1047.21 r0 bottom value=0
R3 "RK73Z1ETTP" 0402L 2997,1012 r0 bottom value=0
R4 "RK73Z1ETTP" 0402L 3224.68,2438 r0 bottom value=0
R5 "RK73Z1ETTP" 0402L 3224,2471 r0 bottom value=0
R6 "RK73Z1ETTP" 0402L 2954.25,2440 r180 bottom value=0
R7 "RK73Z1ETTP" 0402L 2954,2474 r180 bottom value=0
R8 "CRCW040210K0JNED" 0402L 801.18,587 r90 bottom value=10k
R9 "CRCW040210K0JNED" 0402L 902,588 r90 bottom value=10k
R10 "CRCW040210K0JNED" 0402L 1001,587 r90 bottom value=10k
R11 "CRCW040210K0JNED" 0402L 1101,586 r90 bottom value=10k
R12 "CRCW040210K0JNED" 0402L 1201,587 r90 bottom value=10k
R13 "CRCW040210K0JNED" 0402L 1300,588 r90 bottom value=10k
R14 "CRCW040210K0JNED" 0402L 1402,589 r90 bottom value=10k
R15 "CRCW040210K0JNED" 0402L 1501,589 r90 bottom value=10k
R16 "CRCW040210K0JNED" 0402L 1600,589 r90 bottom value=10k
R17 "CRCW040210K0JNED" 0402L 1699,589 r90 bottom value=10k
R18 "CRCW040210K0JNED" 0402L 1801,588 r90 bottom value=10k
R19 "CRCW04021K20JNED" 0402L 3781,2006 r180 bottom value=1.2k
R20 "CRCW0402240RJNED" 0402L 1120,2614.39 r180 bottom value=240
R21 "CRCW0402240RJNED" 0402L 1123.5,2563 r0 bottom value=240
R22 "CRCW04021K20JNED" 0402L 418,2177.17 r180 bottom value=1.2k
R23 "CRCW04021K20JNED" 0402L 419.1,2135.87 r180 bottom value=1.2k
R24 "CRCW04021K20JNED" 0402L 418.7,2094 r180 bottom value=1.2k
R25 "Resistor" 0508S 1121,2692.18 r90 bottom value=0.002
R26 "RK73Z1ETTP" 0402L 903,2853.73 r180 top value=0
R28 "CRCW040210K0JNED" 0402L 1094,1817.18 r0 bottom value=10k
R29 "CRCW040210K0JNED" 0402L 2090,1111.96 r180 bottom value=10k
R30 "CRCW0402240RJNED" 0402L 2310,2167 r180 bottom value=240
R31 "CRCW040210K0JNED" 0402L 320,1905 r0 bottom value=10k
R32 "CRCW0402100RJNED" 0402L 4096,2125 r180 bottom value=100
R33 "CRCW040210K0JNED" 0402L 587,351 r0 bottom value=10k
R34 "CRCW0402200KJNED" 0402 1859,1287 r180 bottom value=200k
R35 "RK73Z1ETTP" 0402L 659,2202.72 r0 bottom value=0
R37 "CRCW040210K0JNED" 0402L 1092.42,1749 r0 bottom value=10k
R38 "CRCW040210K0JNED" 0402L 1092.42,1717 r180 bottom value=10k
R39 "RK73Z1ETTP" 0402L 320,1941 r0 bottom value=0
R40 "RK73Z1ETTP" 0402L 3411.81,1425 r180 bottom value=0
R41 "CRCW04024K87FKED" 0402L 270,982 r180 bottom value=4.87k
R42 "CRCW040210K0JNED" 0402L 365,1205 r0 bottom value=10k
R43 "CRCW04024K87FKED" 0402L 270,953 r180 bottom value=4.87k
R44 "CRCW040210K0JNED" 0402L 1023,1676 r270 bottom value=10k
R45 "CRCW0402100RJNED" 0402L 475,961 r270 bottom value=100
R46 "CRCW040210K0JNED" 0402L 968,733 r180 bottom value=10k
R47 "CRCW040210K0JNED" 0402L 144,708 r90 bottom value=10k
R48 "CRCW04021M00JNED" 0402L 1172,1035.89 r0 bottom value=1.0Meg
R49 "CRCW040210K0JNED" 0402L 1170,1125 r180 bottom value=10k
R50 "CRCW04021K20JNED" 0402L 619,914 r270 bottom value=1.2k
R51 "CRCW0402100RJNED" 0402L 4336.01,2065 r180 bottom value=100
R52 "CRCW04024K87FKED" 0402L 1171,1165.14 r0 bottom value=4.87k
R53 "CRCW0402200KJNED" 0402L 1414.3,1564 r0 bottom value=200k
R54 "CRCW0402100RJNED" 0402L 1856,1414 r0 bottom value=100
R55 "CRCW04021M00JNED" 0402L 1414,1598 r0 bottom value=1.0Meg
R58 "RK73Z1ETTP" 0402L 2522,1954 r180 bottom value=0
R59 "CRCW04021K20JNED" 0402L 532,1975 r180 bottom value=1.2k
R60 "CRCW04021M00JNED" 0402L 247,1129 r180 bottom value=1.0Meg
R61 "CRCW04021K20JNED" 0402L 2026,1214 r180 bottom value=1.2k
R62 "CRCW04021K20JNED" 0402L 2026,1243 r180 bottom value=1.2k
R63 "CRCW04021K20JNED" 0402L 2026,1156 r180 bottom value=1.2k
R64 "CRCW04021K20JNED" 0402L 2026,1185 r180 bottom value=1.2k
R65 "RK73Z1ETTP" 0402L 3718.15,2122 r0 bottom value=0
R66 "CRCW0402374KFKED" 0402L 1414,1630.32 r0 bottom value=374k
R67 "RK73Z1ETTP" 0402L 3754.2,2043.76 r0 bottom value=0
R68 "CRCW04021M00JNED" 0402L 4048.68,1500.19 r180 bottom value=1.0Meg
R69 "CRCW04021M00JNED" 0402L 4049.53,1400 r180 bottom value=1.0Meg
R70 "CRCW040210K0JNED" 0402L 1405,1244 r0 bottom value=10k
R71 "CRCW040210K0JNED" 0402L 1405,1216 r0 bottom value=10k
R72 "CRCW040210K0JNED" 0402L 1405,1187 r0 bottom value=10k
R73 "CRCW040210K0JNED" 0402L 1405,1156 r0 bottom value=10k
R74 "CRCW040210K0JNED" 0402L 849,907 r270 bottom value=10k
R75 "CRCW040210K0JNED" 0402L 938,908 r270 bottom value=10k
R76 "CRCW040210K0JNED" 0402L 365,1236 r180 bottom value=10k
R77 "CRCW040210K0JNED" 0402L 1193.31,1417 r0 bottom value=10k
R78 "CRCW040210K0JNED" 0402L 365,1175 r0 bottom value=10k
R79 "CRCW040210K0JNED" 0402L 620,1678 r270 bottom value=10k
R80 "CRCW040210K0JNED" 0402L 961,1676 r270 bottom value=10k
R81 "CRCW040210K0JNED" 0402L 994,1675 r270 bottom value=10k
R82 "CRCW040210K0JNED" 0402L 1172,1079 r180 bottom value=10k
R83 "RK73Z1ETTP" 0402L 1093,1782 r180 bottom value=0
R93 "CRCW040210K0JNED" 0402L 689.71,1768 r0 bottom value=10k
R94 "CRCW040210K0JNED" 0402L 690,1797 r0 bottom value=10k
R95 "CRCW040210K0JNED" 0402L 691,1836 r180 bottom value=10k
S1 "CL-SB-12A-01T" SW_CL-SB-12A-01 102.12,515 r180 top
S2 "147873-1" SW_147873-1 2178.51,115 r0 top
S3 "218-6LPST" SW_218-6LPST 1601,2642 r180 bottom
SH-J1 "881545-2" TE_881545-2 800,450 r90 top
SH-J2 "881545-2" TE_881545-2 900,450 r90 top
SH-J3 "881545-2" TE_881545-2 1000,450 r90 top
SH-J4 "881545-2" TE_881545-2 1100,450 r90 top
SH-J5 "881545-2" TE_881545-2 1400,450 r90 top
SH-J6 "881545-2" TE_881545-2 1500,450 r90 top
SH-J7 "881545-2" TE_881545-2 1600,450 r90 top
SH-J8 "881545-2" TE_881545-2 1700,450 r90 top
SH-J9 "881545-2" TE_881545-2 1800,450 r90 top
SH-J10 "881545-2" TE_881545-2 100,1530 r90 top
SH-J11 "881545-2" TE_881545-2 2281,1965 r90 top
SH-J12 "881545-2" TE_881545-2 2280,1745 r90 top
SH-J13 "881545-2" TE_881545-2 2280,1520 r90 top
SH-J14 "881545-2" TE_881545-2 1731.81,2167.66 r0 top
SH-J15 "881545-2" TE_881545-2 1160,2170 r0 top
SH-J16 "881545-2" TE_881545-2 3930,2530 r90 top
TP1 "5000" Keystone5000 2436,2373 r90 top
TP2 "5000" Keystone5000 3783,2370 r90 top
TP3 "S1751-46" Harwin_S1751-46 1045.4,1306 r0 top
TP4 "S1751-46" Harwin_S1751-46 1892,2985.3 r0 top
TP5 "S1751-46" Harwin_S1751-46 4460,2990 r0 top
TP6 "5004" Keystone5004 3779,2247 r90 top
TP7 "5004" Keystone5004 2436,2250 r90 top
TP8 "5004" Keystone5004 3931,2125 r90 top
TP9 "5004" Keystone5004 3464.93,1483 r90 top
TP10 "5004" Keystone5004 2695,1373 r90 top
TP11 "5004" Keystone5004 3511,1990 r90 top
TP12 "5004" Keystone5004 2624,2190.35 r90 top
TP13 "5004" Keystone5004 3600,1510 r90 top
TP14 "S1751-46" Harwin_S1751-46 4848,503 r90 top
U1 "TPS65941-Q1" RVJ0056A 3067,1759 r0 top locked
U2 "LM2901AVQPWRQ1" PW0014A_N 895,1826 r180 bottom
U3 "MSP432E401YTPDTR" PDT0128A 788,1299 r270 bottom
U4 "TPD6E004RSER" RSE0008A 313,745 r270 bottom
U5 "TPD4S012DRYR" DRY0006A 563.1,909.37 r180 bottom
U6 "TLV7103318QDSERQ1" DSE0006A 407.44,1849.69 r0 bottom
U7 "TS3A5223RSWR" RSW0010A 1116.06,2032 r270 bottom
U8 "SN74GTL2003PWR" PW0020A_N 1620,1173.04 r180 bottom
U9 "SN74GTL2003PWR" PW0020A_N 1620,1451.35 r180 bottom
U10 "TS3A5223RSWR" RSW0010A 3785,1466 r0 bottom
U11 "TS3A5018RSVR" RSV0016A 2168,1195 r270 bottom
U12 "TS3A5018RSVR" RSV0016A 1265.76,1324.87 r270 bottom
U13 "TLV7103318QDSERQ1" DSE0006A 412.28,2572 r180 bottom
U14 "TPS60110PWPR" PWP0020C_N 402.16,2376 r180 bottom
Y1 "NX3215SD-STD-MUS-6" NDK_NX3215SD 3346,1862 r180 top
Y2 "NX3225GA-25.000M-STD-CRG-2" NDK_NX3225GA 710.25,809.77 r90 bottom
ZZ1 "This Assembly Note is for PCB labels only" AssemblyNoteLabel 132,4145 r0 top
ZZ2 "These assemblies are ESD sensitive, ESD precautions shall be observed." AssemblyNote 132,4000 r0 top
ZZ3 "These assemblies must be clean and free from flux and all contaminants. Use of no clean flux is not acceptable." AssemblyNote 132,3841 r0 top
ZZ4 "These assemblies must comply with workmanship standards IPC-A-610 Class 2, unless otherwise specified." AssemblyNote 132,3672 r0 top

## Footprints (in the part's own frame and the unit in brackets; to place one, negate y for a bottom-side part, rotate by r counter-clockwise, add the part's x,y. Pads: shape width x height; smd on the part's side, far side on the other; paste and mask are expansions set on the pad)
0402 [mm] "0402 from SM-752 data"
  rect 0.8x0.6 smd: 1(-0.6,0) 2(0.6,0)
  silkscreen extent -1.22,-0.52 1.22,0.52, body extent -0.55,-0.3 0.55,0.3, height 0.6
0402L [mm] "0402 from SM-752 data"
  rect 0.6x0.5 smd: 1(-0.5,0) 2(0.5,0)
  body extent -0.55,-0.3 0.55,0.3, height 0.6
0508S [mil] "Small 0508 footprint"
  rrect18% 22x80 smd: 1(-23,0) 2(23,0)
  body extent -29,-43 29,43, height 39
0603L [mm] "0603 from SM-752 data"
  rect 0.8x0.85 smd: 1(-0.7,0) 2(0.7,0)
  silkscreen extent -0.07,-0.33 0.07,0.33, body extent -0.87,-0.47 0.87,0.47, height 1
0603S [mil]
  rect 20x35 smd: 1(-30,0) 2(30,0)
  body extent -34,-19 34,19, height 39
0805L [mm] "0805 from SM-752 data"
  rect 1.1x1.4 smd: 1(-0.75,0) 2(0.75,0)
  body extent -1.1,-0.72 1.1,0.72, height 1.45
1206_180L [mm] "1206_180"
  rect 1.1x1.75 smd: 1(-1.35,0) 2(1.35,0)
  silkscreen extent -0.4,-0.77 0.4,0.77, body extent -1.75,-0.95 1.75,0.95, height 1.8
1206_190 [mm] "1206_190"
  rect 1.1x1.6 smd: 1(-1.7,0) 2(1.7,0)
  silkscreen extent -0.9,-1 0.9,1, body extent -1.75,-0.95 1.75,0.95, height 1.9
1206_190L [mm] "1206_190"
  rect 1.1x1.75 smd: 1(-1.35,0) 2(1.35,0)
  silkscreen extent -0.4,-0.77 0.4,0.77, body extent -1.75,-0.95 1.75,0.95, height 1.9
1210_280 [mm] "SMD, 2-Leads, Body 3.6x2.8mm, Height 2.8mm"
  rect 1.1x2.2 smd: 1(-1.65,0) 2(1.65,0)
  silkscreen extent -0.84,-1.4 0.84,1.4, body extent -1.8,-1.4 1.8,1.4, height 2.8
7343-40 [mm] "Molded, 2-Leads, Body 7.3x4.3mm, Height 4mm"
  rect 2.4x2.9 smd: 1(-3.05,0) 2(3.05,0)
  silkscreen extent -3.8,-2.25 3.8,2.25, body extent -3.8,-2.25 3.8,2.25, height 4.01
Amphenol_12401610E4_2A [mm] "Receptacle, 0.5mm, USB TYPE C, R/A, SMT"
  rect 0.3x0.7 smd: A1(-2.75,0.66) A2(-2.25,0.66) A3(-1.75,0.66) A4(-1.25,0.66) A5(-0.75,0.66) A6(-0.25,0.66) A7(0.25,0.66) A8(0.75,0.66) A9(1.25,0.66) A10(1.75,0.66) A11(2.25,0.66) A12(2.75,0.66) B1(2.5,-1.04) B2(2,-1.04) B3(1.5,-1.04) B4(1,-1.04) B5(0.5,-1.04) B6(0,-1.04) B7(-0.5,-1.04) B8(-1,-1.04) B9(-1.5,-1.04) B10(-2,-1.04) B11(-2.5,-1.04) B12(-3,-1.04)
  round 0 hole 0.65 unplated: ALIGN1(-3.6,0)
  round 0 hole 0.65 slot 0.95 at 0 deg unplated: ALIGN2(3.6,0)
  oval 0.8x1.4 hole 0.5 slot 1.1 at 90 deg: S1(-4.13,-1.25) S2(4.13,-1.25) S3(-4.49,-7.2) S4(4.49,-7.2)
  silkscreen extent -4.6,-9.59 4.6,1.2, body extent -4.59,-9.59 4.59,0.91, height 3.3
AssemblyNote [mil] "Assembly Note"
AssemblyNoteLabel [mil] "Assembly Note for PCB Labels"
CE_Mark_5mm [mil] "Minimum text height for CE Mark"
  silkscreen extent -138,-98 138,98
DRY0006A [mm] "USON-6"
  rrect67% 0.45x0.3 smd paste-0.05 mask-0.05: 1(-0.275,0.5)
  rrect67% 0.4x0.3 smd paste-0.05 mask-0.05: 2(-0.3,0) 3(-0.3,-0.5) 4(0.3,-0.5) 5(0.3,0) 6(0.3,0.5)
  body extent -0.5,-0.72 0.5,0.72, height 0.58
DSE0006A [mm] "TI recommended land pattern"
  rect 0.66x0.25 smd: 1(-0.62,0.5)
  rect 0.7x0.25 smd: 2(-0.6,0) 3(-0.6,-0.5) 4(0.6,-0.5) 5(0.6,0) 6(0.6,0.5)
  Top Layer region: -0.3,0.625 -0.25,0.625 -0.15,0.525 -0.15,0.375 -0.3,0.375
  silkscreen extent -0.9,-0.92 0.9,0.92, body extent -0.77,-0.77 0.77,0.77, height 0.8
DX-H_1150x500 [mm] "Elna horizontal SUPERCAP"
  rect 1.8x1.8 hole 1.1: 1(-5,0)
  round 1.8 hole 1.1: 2(5,0)
  silkscreen extent -7.82,-5.9 3.95,5.9, body extent -7.82,-5.9 5.07,5.9, height 5.5
FCC_disclaimer_stacked [mil]
Fiducial10-30 [mm]
  round 1 smd mask+1: 1(0,0)
  Top Layer keep-out circle w1.678: c0,0 r0.75
FP-ESQ-108-14-T-S_HDR8-MFG [mm]
  rrect6% 1.57x1.57 hole 1.02 paste-1000 mask+0: 1(-8.89,0)
  round 1.57 hole 1.02 paste-1000 mask+0: 2(-6.35,0) 3(-3.81,0) 4(-1.27,0) 5(1.27,0) 6(3.81,0) 7(6.35,0) 8(8.89,0)
  body extent -10.41,-1.28 10.41,1.26, height 11.18
FP-ESQ-111-14-T-S_HDR11-MFG#1 [mm]
  rrect6% 1.57x1.57 hole 1.02 paste-1000 mask+0: 1(-12.7,-0.014)
  round 1.57 hole 1.02 paste-1000 mask+0: 2(-10.16,-0.014) 3(-7.62,-0.014) 4(-5.08,-0.014) 5(-2.54,-0.014) 6(0,-0.014) 7(2.54,-0.014) 8(5.08,-0.014) 9(7.62,-0.014) 10(10.16,-0.014) 11(12.7,-0.014)
  silkscreen extent -14.37,-1.87 14.37,1.27, body extent -14.22,-1.27 14.22,1.27, height 11.3
FP-ESQ-111-14-T-S_HDR11-MFG#2 [mm]
  rrect6% 1.57x1.57 hole 1.02 paste-1000 mask+0: 1(-12.792,0)
  round 1.57 hole 1.02 paste-1000 mask+0: 2(-10.252,0) 3(-7.712,0) 4(-5.172,0) 5(-2.632,0) 6(-0.092,0) 7(2.448,0) 8(4.988,0) 9(7.528,0) 10(10.068,0) 11(12.608,0)
  silkscreen extent -14.37,-1.87 14.37,1.27, body extent -14.22,-1.27 14.22,1.27, height 11.3
FP-GCM1555C1H6R0CA16_0402-MFG [mm]
  rrect25% 0.4x0.5 smd paste+0 mask+0: 1(-0.4,0) 2(0.4,0)
  body extent -0.7,-0.38 0.7,0.38, height 0.25
FP-NFM15HC105D0G3_0402-MFG [mm]
  rrect33% 0.3x0.3 smd paste+0 mask+0: 1(-0.5,0) 3(0.5,0)
  rrect40% 0.25x0.25 smd paste+0 mask+0: 2(0,0.25) 2(0,-0.25)
  body extent -0.75,-0.48 0.75,0.48, height 0.25
Harwin_S1751-46 [mm] "Test Point, Body 3.25x1.65mm"
  rect 3.45x1.85 smd: 1(0,0)
  body extent -1.62,-0.82 1.63,0.82, height 2.05
HARWIN_S1911-46R [mm] "HARWIN"
  rect 2.48x3 smd mask+0.102: 1(-2.69,0) 2(2.69,0)
  silkscreen extent -0.5,-1.5 0.5,1.5, body extent -3.42,-1.25 3.43,1.26, height 0.99
IEC_HotSurface_Small [mil]
  silkscreen extent -107,-93 107,92
Keystone5000 [mil] "For Keystone 500x miniature loop terminals"
  round 80 hole 40: 1(0,0)
  silkscreen extent -52,-52 52,52, body extent -49,-49 49,49, height 182
Keystone5004 [mil] "For Keystone 500x miniature loop terminals"
  round 80 hole 40: 1(0,0)
  silkscreen extent -52,-52 52,52, body extent -49,-49 49,49, height 182
Label_650x200 [mil] "Thermal Transfer Label"
  round 1 on Mech13: 0(0,0)
  silkscreen extent -325,-100 325,100, body extent -325,-100 325,100, height 1
"LB Q39G_BLUE" [mm] "OSRAM"
  rect 0.8x0.8 smd: 1(-0.75,0) 2(0.75,0)
  silkscreen extent 1.3,-0.5 1.52,0.5, body extent -0.85,-0.45 0.85,0.45, height 0.4
NDK_NX3215SD [mm] "SMD, 2-Leads, Body 1.5x3.2mm"
  rrect7% 1.5x1.7 smd: 1(-0.95,0) 2(0.95,0)
  body extent -1.65,-0.8 1.65,0.8, height 0.9
NDK_NX3225GA [mm] "NDK"
  rect 1.2x1.4 smd: 1(-0.8,1.1) 2(-0.8,-1.1) 3(0.8,-1.1) 4(0.8,1.1)
  silkscreen extent -1.9,-0.1 1.4,2, body extent -1.3,-1.65 1.3,1.65, height 0.9
Net-Tie_0805_HV_NoOverlay [mil] "0805_HV pads tied by 10mil copper trace which can be cut.  An 0805 part can be placed on pads."
  rect 50x63 on Mid2 paste-25: 1(-40,0) 2(40,0)
  Signal Layer 2 lines w10: -16,0 16,0
  Signal Layer 2 keep-out lines w1: -22,-30.91 -22,30.91 ; -14.96,-30.91 14.96,-30.91 ; -14.96,30.91 14.96,30.91 ; 22,-30.91 22,30.91
NFM18HC [mm] "SMD, 2-Leads, Body 1.6x0.8mm"
  rrect17% 0.6x0.7 smd mask+0: 1(-0.8,0) 3(0.8,0)
  rrect25% 0.4x1.2 smd paste-0.2 mask-0.2: 2(0,0)
  body extent -0.9,-0.5 0.9,0.5, height 1.35
PDT0128A [mm] "Thin QFP, 128-Leads, Body 14x14mm, Pitch 0.4mm"
  oval 1.4x0.2 smd: 1(-7.7,6.2) 2(-7.7,5.8) 3(-7.7,5.4) 4(-7.7,5) 5(-7.7,4.6) 6(-7.7,4.2) 7(-7.7,3.8) 8(-7.7,3.4) 9(-7.7,3) 10(-7.7,2.6) 11(-7.7,2.2) 12(-7.7,1.8) 13(-7.7,1.4) 14(-7.7,1) 15(-7.7,0.6) 16(-7.7,0.2) 17(-7.7,-0.2) 18(-7.7,-0.6) 19(-7.7,-1) 20(-7.7,-1.4) 21(-7.7,-1.8) 22(-7.7,-2.2) 23(-7.7,-2.6) 24(-7.7,-3) 25(-7.7,-3.4) 26(-7.7,-3.8) 27(-7.7,-4.2) 28(-7.7,-4.6) 29(-7.7,-5) 30(-7.7,-5.4) 31(-7.7,-5.8) 32(-7.7,-6.2) 65(7.7,-6.2) 66(7.7,-5.8) 67(7.7,-5.4) 68(7.7,-5) 69(7.7,-4.6) 70(7.7,-4.2) 71(7.7,-3.8) 72(7.7,-3.4) 73(7.7,-3) 74(7.7,-2.6) 75(7.7,-2.2) 76(7.7,-1.8) 77(7.7,-1.4) 78(7.7,-1) 79(7.7,-0.6) 80(7.7,-0.2) 81(7.7,0.2) 82(7.7,0.6) 83(7.7,1) 84(7.7,1.4) 85(7.7,1.8) 86(7.7,2.2) 87(7.7,2.6) 88(7.7,3) 89(7.7,3.4) 90(7.7,3.8) 91(7.7,4.2) 92(7.7,4.6) 93(7.7,5) 94(7.7,5.4) 95(7.7,5.8) 96(7.7,6.2)
  oval 0.2x1.4 smd: 33(-6.2,-7.7) 34(-5.8,-7.7) 35(-5.4,-7.7) 36(-5,-7.7) 37(-4.6,-7.7) 38(-4.2,-7.7) 39(-3.8,-7.7) 40(-3.4,-7.7) 41(-3,-7.7) 42(-2.6,-7.7) 43(-2.2,-7.7) 44(-1.8,-7.7) 45(-1.4,-7.7) 46(-1,-7.7) 47(-0.6,-7.7) 48(-0.2,-7.7) 49(0.2,-7.7) 50(0.6,-7.7) 51(1,-7.7) 52(1.4,-7.7) 53(1.8,-7.7) 54(2.2,-7.7) 55(2.6,-7.7) 56(3,-7.7) 57(3.4,-7.7) 58(3.8,-7.7) 59(4.2,-7.7) 60(4.6,-7.7) 61(5,-7.7) 62(5.4,-7.7) 63(5.8,-7.7) 64(6.2,-7.7) 97(6.2,7.7) 98(5.8,7.7) 99(5.4,7.7) 100(5,7.7) 101(4.6,7.7) 102(4.2,7.7) 103(3.8,7.7) 104(3.4,7.7) 105(3,7.7) 106(2.6,7.7) 107(2.2,7.7) 108(1.8,7.7) 109(1.4,7.7) 110(1,7.7) 111(0.6,7.7) 112(0.2,7.7) 113(-0.2,7.7) 114(-0.6,7.7) 115(-1,7.7) 116(-1.4,7.7) 117(-1.8,7.7) 118(-2.2,7.7) 119(-2.6,7.7) 120(-3,7.7) 121(-3.4,7.7) 122(-3.8,7.7) 123(-4.2,7.7) 124(-4.6,7.7) 125(-5,7.7) 126(-5.4,7.7) 127(-5.8,7.7) 128(-6.2,7.7)
  silkscreen extent -7.7,-6.3 6.3,6.99, body extent -8,-8 8,8, height 1.07
Phoenix_1792863 [mm] "Terminal Block, 5mm, 2x1, R/A, TH"
  rrect50% 1.7x1.7 hole 1.2: 1(-2.5,0)
  round 1.7 hole 1.2: 2(2.5,0)
  silkscreen extent -5.6,-4.95 5,5.55, body extent -5,-4.95 5,5.55, height 13.6
PW0014A_N [mm] "TSOP, 14-Leads, Body 5x4.4mm, Pitch 0.65mm, IPC Medium Density"
  oval 1.4x0.45 smd: 1(-2.95,1.95) 2(-2.95,1.3) 3(-2.95,0.65) 4(-2.95,0) 5(-2.95,-0.65) 6(-2.95,-1.3) 7(-2.95,-1.95) 8(2.95,-1.95) 9(2.95,-1.3) 10(2.95,-0.65) 11(2.95,0) 12(2.95,0.65) 13(2.95,1.3) 14(2.95,1.95)
  silkscreen extent -3.4,-2.55 1.85,2.55, body extent -3.21,-2.5 3.21,2.5, height 1
PW0020A_N [mm] "TSOP, 20-Leads, Body 6.5x4.4mm, Pitch 0.65mm, IPC Medium Density"
  oval 1.4x0.45 smd: 1(-2.95,2.925) 2(-2.95,2.275) 3(-2.95,1.625) 4(-2.95,0.975) 5(-2.95,0.325) 6(-2.95,-0.325) 7(-2.95,-0.975) 8(-2.95,-1.625) 9(-2.95,-2.275) 10(-2.95,-2.925) 11(2.95,-2.925) 12(2.95,-2.275) 13(2.95,-1.625) 14(2.95,-0.975) 15(2.95,-0.325) 16(2.95,0.325) 17(2.95,0.975) 18(2.95,1.625) 19(2.95,2.275) 20(2.95,2.925)
  Top Overlay keep-out lines w0.2: 1.85,-3.3 -1.85,-3.3
  silkscreen extent -3.5,-3.3 1.85,3.4, body extent -3.21,-3.25 3.21,3.25, height 1
PWP0020C_N [mm] "SOP, 20-Leads, Body 6.4x4.4mm, Pitch 0.65mm, Thermal Pad 1.95x2.675mm, IPC Medium Density"
  rrect22% 1.4x0.45 smd: 1(-2.95,2.925) 2(-2.95,2.275) 3(-2.95,1.625) 4(-2.95,0.975) 5(-2.95,0.325) 6(-2.95,-0.325) 7(-2.95,-0.975) 8(-2.95,-1.625) 9(-2.95,-2.275) 10(-2.95,-2.925) 11(2.95,-2.925) 12(2.95,-2.275) 13(2.95,-1.625) 14(2.95,-0.975) 15(2.95,-0.325) 16(2.95,0.325) 17(2.95,0.975) 18(2.95,1.625) 19(2.95,2.275) 20(2.95,2.925)
  rrect6% 3.4x6.5 smd paste-2 mask-2: 21(0,0)
  rrect4% 2.4x3.38 on Bottom Paste: 21(0,0)
  rrect4% 2.4x3.38 on Bottom Solder: 21(0,0)
  silkscreen extent -3.55,-3.3 1.5,3.4, body extent -3.21,-3.25 3.21,3.25, height 1
RSE0008A [mm] "QFN, 8-Leads, Body 1.5x1.5mm, Pitch 0.5mm, TI Recommended"
  rrect40% 0.55x0.25 smd: 1(-0.675,0.5) 3(-0.675,-0.5) 5(0.675,-0.5) 7(0.675,0.5)
  rrect50% 0.55x0.2 smd: 2(-0.675,0) 6(0.675,0)
  rrect33% 0.3x0.6 smd: 4(0,-0.65) 8(0,0.65)
  silkscreen extent -1.02,-0.92 0.77,0.93, body extent -0.75,-0.75 0.75,0.75, height 0.6
RSV0016A [mm] "QFN, 16-Leads, Body 1.8x2.6mm, Pitch 0.4mm, TI Recommended"
  rect 0.7x0.2 smd: 1(-0.75,0.6)
  rect 0.6x0.2 smd: 2(-0.8,0.2) 3(-0.8,-0.2) 4(-0.8,-0.6) 9(0.8,-0.6) 10(0.8,-0.2) 11(0.8,0.2) 12(0.8,0.6)
  rect 0.2x0.6 smd: 5(-0.6,-1.2) 6(-0.2,-1.2) 7(0.2,-1.2) 8(0.6,-1.2) 13(0.6,1.2) 14(0.2,1.2) 15(-0.2,1.2) 16(-0.6,1.2)
  silkscreen extent -1.08,-1.33 1.08,1.45, body extent -0.92,-1.32 0.92,1.33, height 0.56
RSW0010A [mm] "QFN, 10-Leads, Body 1.8x1.4 mm, Pitch 0.4mm, TI Recommended"
  rrect50% 0.7x0.2 smd: 1(-0.55,0.2)
  rrect50% 0.6x0.2 smd: 2(-0.6,-0.2) 6(0.6,-0.2) 7(0.6,0.2)
  rrect50% 0.2x0.6 smd: 3(-0.4,-0.8) 4(0,-0.8) 5(0.4,-0.8) 8(0.4,0.8) 9(0,0.8) 10(-0.4,0.8)
  silkscreen extent -0.88,-1.08 0.88,1.08, body extent -0.7,-0.9 0.7,0.9, height 0.56
RVJ0056A [mm] "QFN, 56-Leads, Body 8.00x8.00mm, Pitch 0.50mm, Thermal Pad 5.20x5.20mm"
  rrect100% 0.6x0.24 smd: 1(-3.9,3.25) 2(-3.9,2.75) 3(-3.9,2.25) 4(-3.9,1.75) 5(-3.9,1.25) 6(-3.9,0.75) 7(-3.9,0.25) 8(-3.9,-0.25) 9(-3.9,-0.75) 10(-3.9,-1.25) 11(-3.9,-1.75) 12(-3.9,-2.25) 13(-3.9,-2.75) 14(-3.9,-3.25) 29(3.9,-3.25) 30(3.9,-2.75) 31(3.9,-2.25) 32(3.9,-1.75) 33(3.9,-1.25) 34(3.9,-0.75) 35(3.9,-0.25) 36(3.9,0.25) 37(3.9,0.75) 38(3.9,1.25) 39(3.9,1.75) 40(3.9,2.25) 41(3.9,2.75) 42(3.9,3.25)
  rrect100% 0.24x0.6 smd: 15(-3.25,-3.9) 16(-2.75,-3.9) 17(-2.25,-3.9) 18(-1.75,-3.9) 19(-1.25,-3.9) 20(-0.75,-3.9) 21(-0.25,-3.9) 22(0.25,-3.9) 23(0.75,-3.9) 24(1.25,-3.9) 25(1.75,-3.9) 26(2.25,-3.9) 27(2.75,-3.9) 28(3.25,-3.9) 43(3.25,3.9) 44(2.75,3.9) 45(2.25,3.9) 46(1.75,3.9) 47(1.25,3.9) 48(0.75,3.9) 49(0.25,3.9) 50(-0.25,3.9) 51(-0.75,3.9) 52(-1.25,3.9) 53(-1.75,3.9) 54(-2.25,3.9) 55(-2.75,3.9) 56(-3.25,3.9)
  rrect2% 5.2x5.2 smd paste-5: 57(0,0)
  silkscreen extent -4.23,-4.23 4.22,4.23, body extent -4.08,-4.07 4.07,4.08, height 1.02
Samtec_FTSH-105-01-x-DV-K [mm] "Header(Shrouded), 1.27mm, 5x2, SMT"
  rect 2.79x0.74 smd: 1(-2.035,2.54) 2(2.035,2.54) 3(-2.035,1.27) 4(2.035,1.27) 5(-2.035,0) 6(2.035,0) 7(-2.035,-1.27) 8(2.035,-1.27) 9(-2.035,-2.54) 10(2.035,-2.54)
  silkscreen extent -3.73,-3.48 3.73,3.48, body extent -2.92,-3.18 2.92,3.17, height 6.13
SAMTEC_SMA-J-P-H-ST-TH1 [mm] "TH, 5-Leads, Body 7x7mm"
  round 2.1 hole 1.6: 1(0,0) 2(-2.54,2.54) 3(2.54,2.54) 4(2.54,-2.54) 5(-2.54,-2.54)
  silkscreen extent -3.5,-3.5 3.5,3.5, body extent -3.5,-3.5 3.5,3.5, height 9.55
Samtec_TSM-102-01-T-SV-P-TR [mil] "SMD, 2-Leads, Body 200x100mil"
  rect 50x135 smd: 1(-50,57.5) 2(50,-57.5)
  silkscreen extent -100,-50 100,92, body extent -100,-97 100,96, height 380
Samtec_TSM-103-01-X-SV [mil] "Samtec recommended land pattern"
  rect 50x135 smd: 1(-100,57.5) 2(0,-57.5) 3(100,57.5)
  silkscreen extent -150,-50 150,50, body extent -150,-104 150,104, height 381
Samtec_TSW-102-23-X-S [mm] "Header, 2.54mm, 2x1, TH"
  rrect50% 1.53x1.53 hole 1.02: 1(-1.27,0)
  round 1.53 hole 1.02: 2(1.27,0)
  body extent -2.67,-1.27 2.54,1.27, height 8.38
SM_RADIAL_8MM [mm] "Nichicon 8x10"
  rect 3.5x2.5 smd: 1(-3.25,0) 2(3.25,0)
  silkscreen extent -4.25,-4.25 4.25,4.25, body extent -4.25,-4.25 4.25,4.25, height 10.5
SO-8FL [mm] "ON SEMICONDUCTOR, DFN5 5x6, 1.27P, CASE 488AA"
  rect 1x0.75 smd: 1(-2.795,1.905) 2(-2.795,0.635) 3(-2.795,-0.635) 4(-2.795,-1.905)
  rect 4.055x4.56 smd: 5(0.698,0)
  Top Layer region: 3.199,-2.28 3.199,-1.53 2.649,-1.53 2.649,-2.28
  Top Layer region: 3.199,1.53 3.199,2.28 2.654,2.28 2.654,1.53
  Top Layer region: 0,-2.775 0,2.775 -0.905,2.775 -0.905,-2.775
  silkscreen extent -3.1,-2.6 3.1,2.9, body extent -3.17,-2.67 3.17,2.67, height 1.11
SOD-323 [mm] "NXP recommended land pattern"
  rect 0.6x0.6 smd paste-0.05: 1(-1.1,0) 2(1.1,0)
  silkscreen extent -2.06,-0.86 1.53,0.86, body extent -1.3,-0.67 1.3,0.68, height 1.1
SW_218-6LPST [mm] "SMD, 12-Leads, Body 5.8x8.79mm"
  rect 1.27x0.76 smd: 1(-3.81,3.175) 2(-3.81,1.905) 3(-3.81,0.635) 4(-3.81,-0.635) 5(-3.81,-1.905) 6(-3.81,-3.175) 7(3.81,-3.175) 7(3.81,-3.175) 8(3.81,-1.905) 9(3.81,-0.635) 10(3.81,0.635) 11(3.81,1.905) 12(3.81,3.175)
  silkscreen extent -2.9,-4.4 2.9,4.7, body extent -4.22,-4.4 4.22,4.39, height 2.62
SW_147873-1 [mm] "SMD, 2-Leads, Body 6x3.5mm"
  rect 2.8x2.2 smd: 1(-2.4,0) 2(2.4,0)
  silkscreen extent -2.93,-1.75 2.93,1.75, body extent -3.4,-1.75 3.4,1.75, height 5.2
SW_CL-SB-12A-01 [mm] "SMD, 3-Leads, Body 8.5x3.5mm, Pitch 2.5mm"
  rect 1.6x1.2 smd: 1(-1.4,2.5) 2(1.4,0) 3(-1.4,-2.5)
  round 0 hole 0.9 unplated: MH1(0,3.4) MH2(0,-3.4)
  silkscreen extent -2.88,-4.25 1.75,4.25, body extent -1.75,-4.25 1.75,4.25, height 5.5
TE_881545-2 [mil] "TE"
  round 1 on Mech3: 0(0,0)
  body extent -99,-49 99,49, height 530
TFM322512 [mm] "TDK inductor"
  rrect13% 0.8x2.5 smd: 1(-1.4,0) 2(1.4,0)
  body extent -1.7,-1.35 1.7,1.35, height 1.2
TI_Stacked_Overlay_Small [mil]
  silkscreen extent -418,-98 418,98
TSW-107-XX-XXX-S [mm] "2.54mm pitch, 7 pin, terminal strip; straight, single row"
  rrect6% 1.65x1.65 hole 1: 1(-7.62,-0.025)
  round 1.65 hole 1: 2(-5.08,0) 3(-2.54,0) 4(0,0) 5(2.54,0) 6(5.08,0) 7(7.62,0)
  silkscreen extent -9.59,-1.25 8.93,1.25, body extent -8.89,-1.27 8.89,1.27, height 8.38
TSW-111-07-G-S [mm] "Samtec 100mil, 1x11, 230 mil above insulator"
  rrect6% 1.65x1.65 hole 1.016: 1(-12.7,0)
  round 1.65 hole 1.016: 2(-10.16,0) 3(-7.62,0) 4(-5.08,0) 5(-2.54,0) 6(0,0) 7(2.54,0) 8(5.08,0) 9(7.62,0) 10(10.16,0) 11(12.7,0)
  silkscreen extent -13.97,-1.27 13.97,1.65, body extent -13.97,-1.27 13.97,1.27, height 8.38
WEEE_Minimum [mil] "WEEElie bin"
  silkscreen extent -95,-172 99,104
WURTH_61300311121#1 [mm] "Header, 2.54mm, 3x1, TH"
  rrect50% 1.65x1.65 hole 1.15: 1(-2.54,0)
  round 1.65 hole 1.15: 2(0,0) 3(2.54,0)
  body extent -3.81,-1.27 3.81,1.27, height 8.54
WURTH_61300311121#2 [mm] "Header, 2.54mm, 3x1, TH"
  rrect6% 1.57x1.57 hole 1.02 paste-1000 mask+0: 1(-2.54,0)
  round 1.65 hole 1.15: 2(0,0) 3(2.54,0)
  body extent -3.81,-1.27 3.81,1.27, height 8.54
YJC0003A [mm] "TI"
  rrect50% 0.25x0.2 on Bottom Paste: 0(-0.325,-0.2) 0(-0.325,0.2)
  rrect80% 0.35x0.25 smd paste-0.13 mask-0.05: 1(-0.325,0.175) 2(-0.325,-0.175)
  rrect57% 0.35x0.6 smd paste-0.05 mask-0.05: 3(0.325,0)
  body extent -0.5,-0.3 0.5,0.3, height 0.35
